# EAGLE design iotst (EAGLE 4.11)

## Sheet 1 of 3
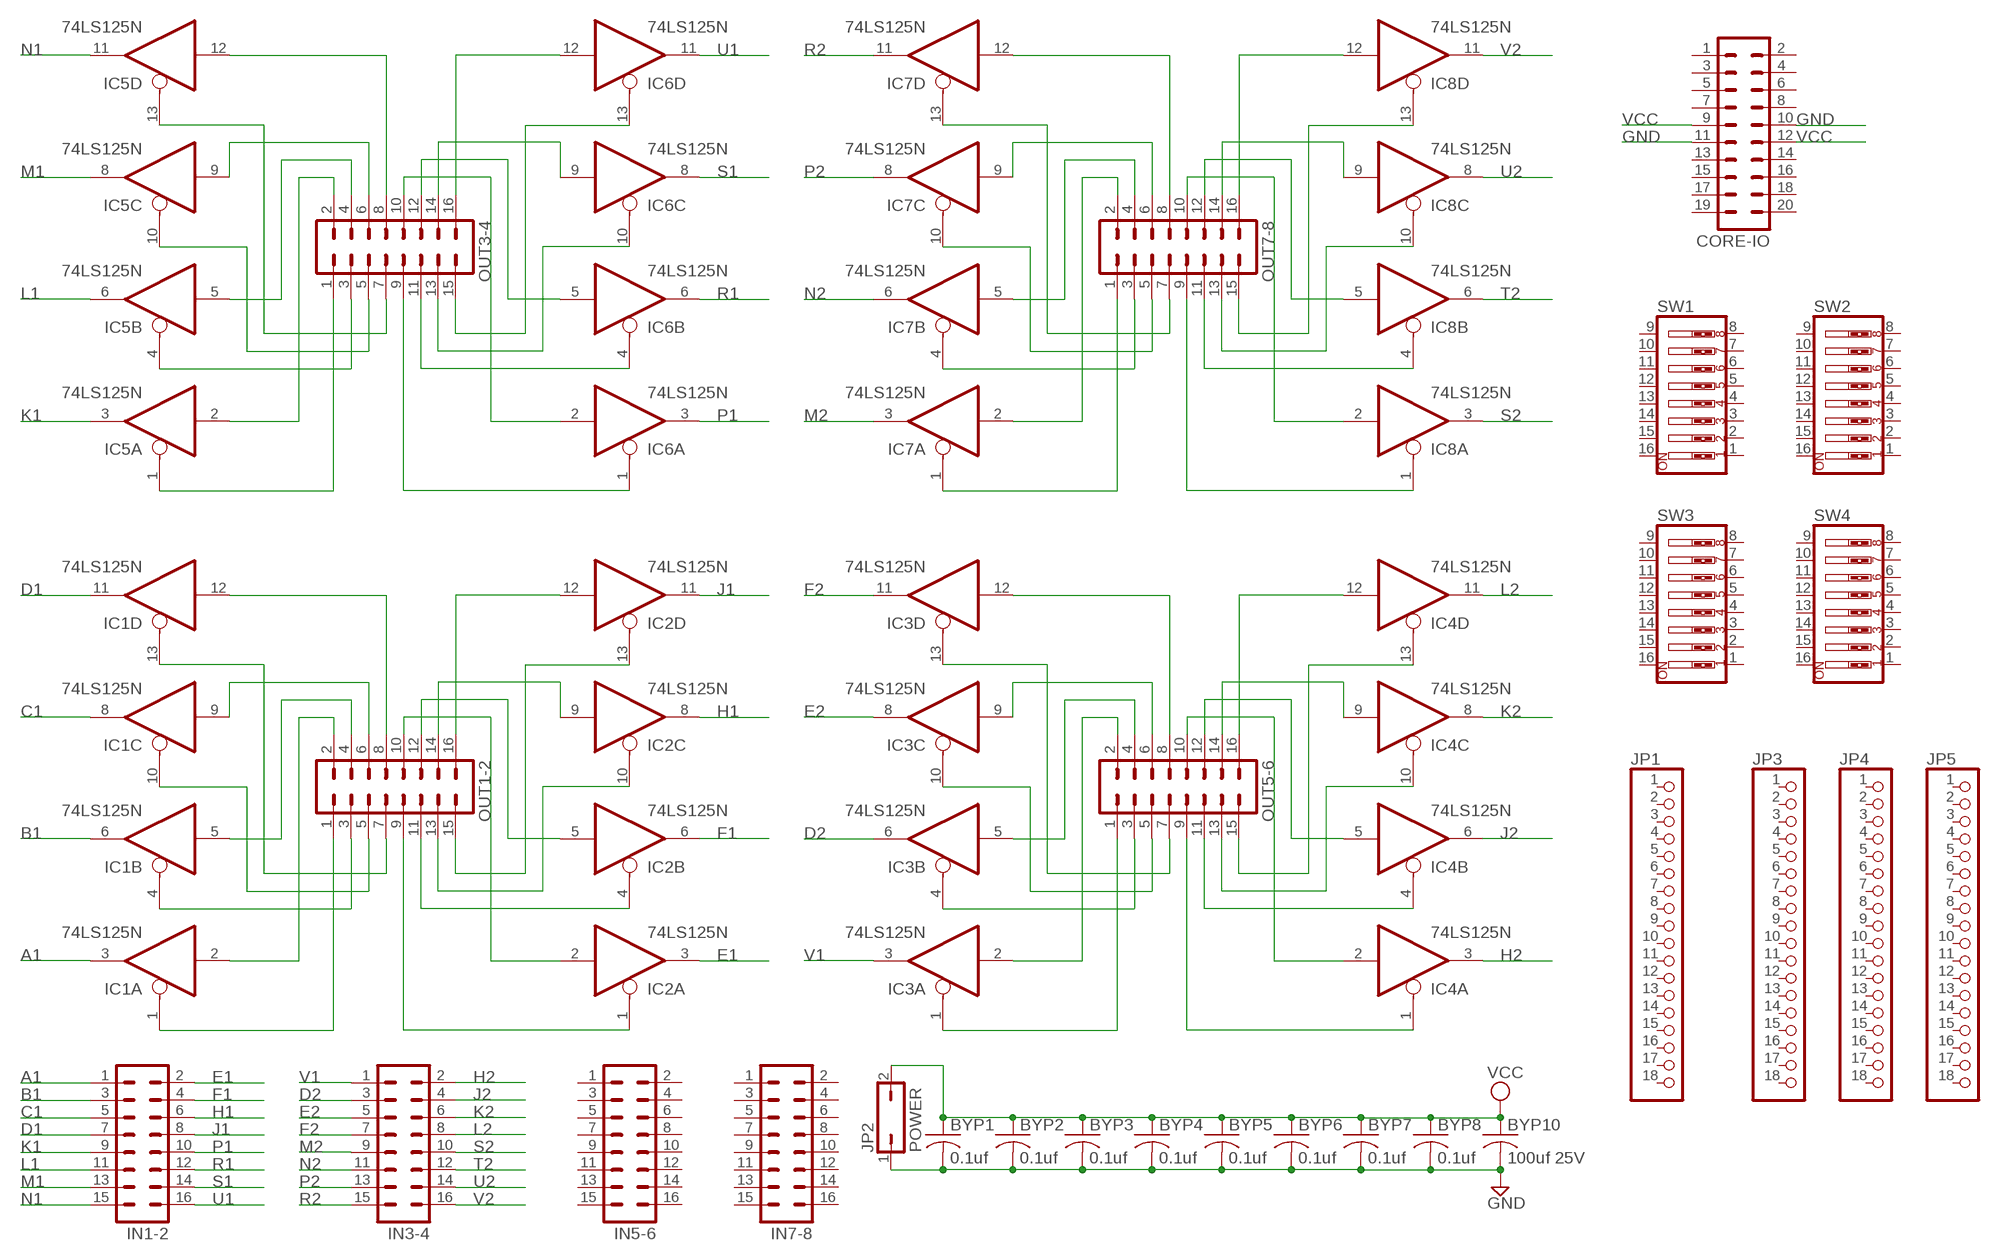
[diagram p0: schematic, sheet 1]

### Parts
BYP1  0.1uf  C-US050-025X075  [C050-025X075]
BYP2  0.1uf  C-US050-025X075  [C050-025X075]
BYP3  0.1uf  C-US050-025X075  [C050-025X075]
BYP4  0.1uf  C-US050-025X075  [C050-025X075]
BYP5  0.1uf  C-US050-025X075  [C050-025X075]
BYP6  0.1uf  C-US050-025X075  [C050-025X075]
BYP7  0.1uf  C-US050-025X075  [C050-025X075]
BYP8  0.1uf  C-US050-025X075  [C050-025X075]
BYP10  100uf 25V  C-US150-064X183  [C150-064X183]
CORE-IO  MA10-2  [MA10-2]
IC1  74LS125N  [DIL14]
IC2  74LS125N  [DIL14]
IC3  74LS125N  [DIL14]
IC4  74LS125N  [DIL14]
IC5  74LS125N  [DIL14]
IC6  74LS125N  [DIL14]
IC7  74LS125N  [DIL14]
IC8  74LS125N  [DIL14]
IN1-2  MA08-2  [MA08-2]
IN3-4  MA08-2  [MA08-2]
IN5-6  MA08-2  [MA08-2]
IN7-8  MA08-2  [MA08-2]
JP1  PINHD-1X18  [1X18]
JP2  POWER  JP1Q  [JP1]
JP3  PINHD-1X18  [1X18]
JP4  PINHD-1X18  [1X18]
JP5  PINHD-1X18  [1X18]
OUT1-2  MA08-2  [MA08-2]
OUT3-4  MA08-2  [MA08-2]
OUT5-6  MA08-2  [MA08-2]
OUT7-8  MA08-2  [MA08-2]
SW1  SW_DIP-8  [EDG-08]
SW2  SW_DIP-8  [EDG-08]
SW3  SW_DIP-8  [EDG-08]
SW4  SW_DIP-8  [EDG-08]

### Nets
A1: IC1.3(A:O) IN1-2.1 ; also sheet 3
B1: IC1.6(B:O) IN1-2.3 ; also sheet 3
C1: IC1.8(C:O) IN1-2.5 ; also sheet 3
D1: IC1.11(D:O) IN1-2.7 ; also sheet 3
D2: IC3.6(B:O) IN3-4.3 ; also sheet 3
E1: IC2.3(A:O) IN1-2.2 ; also sheet 3
E2: IC3.8(C:O) IN3-4.5 ; also sheet 3
F1: IC2.6(B:O) IN1-2.4 ; also sheet 3
F2: IC3.11(D:O) IN3-4.7 ; also sheet 3
GND [Power]: BYP1.2 BYP2.2 BYP3.2 BYP4.2 BYP5.2 BYP6.2 BYP7.2 BYP8.2 BYP10.2 CORE-IO.10 CORE-IO.11 JP2.1 ; also sheet 3
H1: IC2.8(C:O) IN1-2.6 ; also sheet 3
H2: IC4.3(A:O) IN3-4.2 ; also sheet 3
J1: IC2.11(D:O) IN1-2.8 ; also sheet 3
J2: IC4.6(B:O) IN3-4.4 ; also sheet 3
K1: IC5.3(A:O) IN1-2.9 ; also sheet 3
K2: IC4.8(C:O) IN3-4.6 ; also sheet 3
L1: IC5.6(B:O) IN1-2.11 ; also sheet 3
L2: IC4.11(D:O) IN3-4.8 ; also sheet 3
M1: IC5.8(C:O) IN1-2.13 ; also sheet 3
M2: IC7.3(A:O) IN3-4.9 ; also sheet 3
N1: IC5.11(D:O) IN1-2.15 ; also sheet 3
N2: IC7.6(B:O) IN3-4.11 ; also sheet 3
N$53: IC1.1(A:OE) OUT1-2.1
N$54: IC1.4(B:OE) OUT1-2.3
N$55: IC1.10(C:OE) OUT1-2.5
N$56: IC1.13(D:OE) OUT1-2.7
N$57: IC1.2(A:I) OUT1-2.2
N$58: IC1.5(B:I) OUT1-2.4
N$59: IC1.9(C:I) OUT1-2.6
N$60: IC1.12(D:I) OUT1-2.8
N$61: IC3.4(B:OE) OUT5-6.3
N$62: IC2.10(C:OE) OUT1-2.13
N$63: IC2.4(B:OE) OUT1-2.11
N$64: IC2.1(A:OE) OUT1-2.9
N$65: IC2.2(A:I) OUT1-2.10
N$66: IC2.5(B:I) OUT1-2.12
N$67: IC2.9(C:I) OUT1-2.14
N$68: IC2.12(D:I) OUT1-2.16
N$138: IC3.13(D:OE) OUT5-6.7
N$139: IC2.13(D:OE) OUT1-2.15
N$140: IC3.2(A:I) OUT5-6.2
N$141: IC3.5(B:I) OUT5-6.4
N$142: IC3.9(C:I) OUT5-6.6
N$143: IC3.12(D:I) OUT5-6.8
N$144: IC4.10(C:OE) OUT5-6.13
N$145: IC4.4(B:OE) OUT5-6.11
N$146: IC4.1(A:OE) OUT5-6.9
N$147: IC4.2(A:I) OUT5-6.10
N$148: IC4.9(C:I) OUT5-6.14
N$149: IC4.12(D:I) OUT5-6.16
N$150: IC3.1(A:OE) OUT5-6.1
N$151: IC3.10(C:OE) OUT5-6.5
N$152: IC4.5(B:I) OUT5-6.12
N$153: IC4.13(D:OE) OUT5-6.15
N$154: IC5.4(B:OE) OUT3-4.3
N$155: IC5.13(D:OE) OUT3-4.7
N$156: IC5.2(A:I) OUT3-4.2
N$157: IC5.5(B:I) OUT3-4.4
N$158: IC5.9(C:I) OUT3-4.6
N$159: IC5.12(D:I) OUT3-4.8
N$160: IC6.10(C:OE) OUT3-4.13
N$161: IC6.4(B:OE) OUT3-4.11
N$162: IC6.1(A:OE) OUT3-4.9
N$163: IC6.2(A:I) OUT3-4.10
N$164: IC6.9(C:I) OUT3-4.14
N$165: IC6.12(D:I) OUT3-4.16
N$166: IC5.1(A:OE) OUT3-4.1
N$167: IC5.10(C:OE) OUT3-4.5
N$168: IC6.5(B:I) OUT3-4.12
N$169: IC6.13(D:OE) OUT3-4.15
N$170: IC7.4(B:OE) OUT7-8.3
N$171: IC7.13(D:OE) OUT7-8.7
N$172: IC7.2(A:I) OUT7-8.2
N$173: IC7.5(B:I) OUT7-8.4
N$174: IC7.9(C:I) OUT7-8.6
N$175: IC7.12(D:I) OUT7-8.8
N$176: IC8.10(C:OE) OUT7-8.13
N$177: IC8.4(B:OE) OUT7-8.11
N$178: IC8.1(A:OE) OUT7-8.9
N$179: IC8.2(A:I) OUT7-8.10
N$180: IC8.9(C:I) OUT7-8.14
N$181: IC8.12(D:I) OUT7-8.16
N$182: IC7.1(A:OE) OUT7-8.1
N$183: IC7.10(C:OE) OUT7-8.5
N$184: IC8.5(B:I) OUT7-8.12
N$185: IC8.13(D:OE) OUT7-8.15
P1: IC6.3(A:O) IN1-2.10 ; also sheet 3
P2: IC7.8(C:O) IN3-4.13 ; also sheet 3
R1: IC6.6(B:O) IN1-2.12 ; also sheet 3
R2: IC7.11(D:O) IN3-4.15 ; also sheet 3
S1: IC6.8(C:O) IN1-2.14 ; also sheet 3
S2: IC8.3(A:O) IN3-4.10 ; also sheet 3
T2: IC8.6(B:O) IN3-4.12 ; also sheet 3
U1: IC6.11(D:O) IN1-2.16 ; also sheet 3
U2: IC8.8(C:O) IN3-4.14 ; also sheet 3
V1: IC3.3(A:O) IN3-4.1 ; also sheet 3
V2: IC8.11(D:O) IN3-4.16 ; also sheet 3
VCC [Power]: BYP1.1 BYP2.1 BYP3.1 BYP4.1 BYP5.1 BYP6.1 BYP7.1 BYP8.1 BYP10.1 CORE-IO.9 CORE-IO.12 JP2.2 ; also sheet 3
Unconnected: CORE-IO.1 CORE-IO.2 CORE-IO.3 CORE-IO.4 CORE-IO.5 CORE-IO.6 CORE-IO.7 CORE-IO.8 CORE-IO.13 CORE-IO.14 CORE-IO.15 CORE-IO.16 CORE-IO.17 CORE-IO.18 CORE-IO.19 CORE-IO.20 IN5-6.1 IN5-6.2 IN5-6.3 IN5-6.4 IN5-6.5 IN5-6.6 IN5-6.7 IN5-6.8 IN5-6.9 IN5-6.10 IN5-6.11 IN5-6.12 IN5-6.13 IN5-6.14 IN5-6.15 IN5-6.16 IN7-8.1 IN7-8.2 IN7-8.3 IN7-8.4 IN7-8.5 IN7-8.6 IN7-8.7 IN7-8.8 IN7-8.9 IN7-8.10 IN7-8.11 IN7-8.12 IN7-8.13 IN7-8.14 IN7-8.15 IN7-8.16 JP1.1 JP1.2 JP1.3 JP1.4 JP1.5 JP1.6 JP1.7 JP1.8 JP1.9 JP1.10 JP1.11 JP1.12 JP1.13 JP1.14 JP1.15 JP1.16 JP1.17 JP1.18 JP3.1 JP3.2 JP3.3 JP3.4 JP3.5 JP3.6 JP3.7 JP3.8 JP3.9 JP3.10 JP3.11 JP3.12 JP3.13 JP3.14 JP3.15 JP3.16 JP3.17 JP3.18 JP4.1 JP4.2 JP4.3 JP4.4 JP4.5 JP4.6 JP4.7 JP4.8 JP4.9 JP4.10 JP4.11 JP4.12 JP4.13 JP4.14 JP4.15 JP4.16 JP4.17 JP4.18 JP5.1 JP5.2 JP5.3 JP5.4 JP5.5 JP5.6 JP5.7 JP5.8 JP5.9 JP5.10 JP5.11 JP5.12 JP5.13 JP5.14 JP5.15 JP5.16 JP5.17 JP5.18 SW1.1 SW1.2 SW1.3 SW1.4 SW1.5 SW1.6 SW1.7 SW1.8 SW1.9 SW1.10 SW1.11 SW1.12 SW1.13 SW1.14 SW1.15 SW1.16 SW2.1 SW2.2 SW2.3 SW2.4 SW2.5 SW2.6 SW2.7 SW2.8 SW2.9 SW2.10 SW2.11 SW2.12 SW2.13 SW2.14 SW2.15 SW2.16 SW3.1 SW3.2 SW3.3 SW3.4 SW3.5 SW3.6 SW3.7 SW3.8 SW3.9 SW3.10 SW3.11 SW3.12 SW3.13 SW3.14 SW3.15 SW3.16 SW4.1 SW4.2 SW4.3 SW4.4 SW4.5 SW4.6 SW4.7 SW4.8 SW4.9 SW4.10 SW4.11 SW4.12 SW4.13 SW4.14 SW4.15 SW4.16

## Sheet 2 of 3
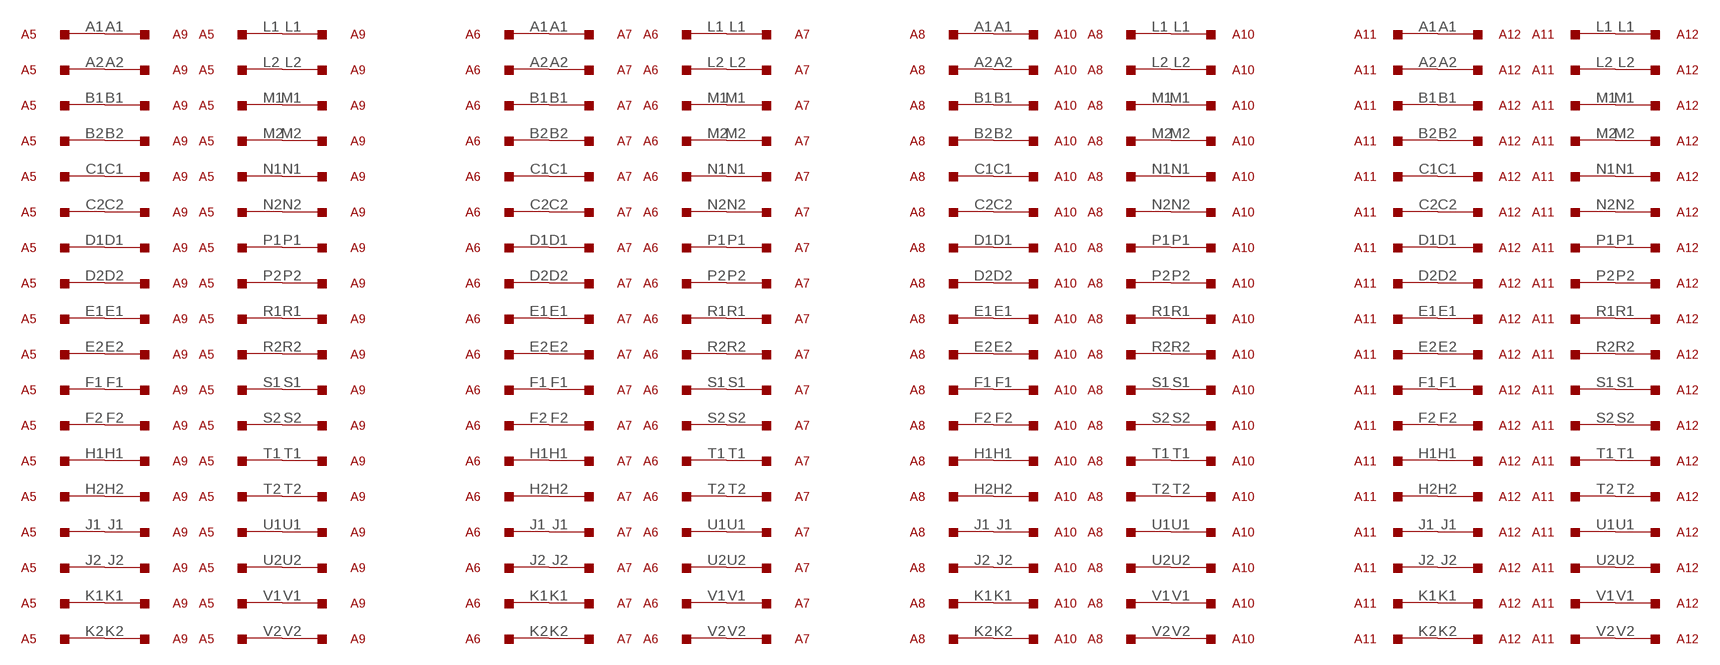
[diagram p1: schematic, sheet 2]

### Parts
A5  M916  [H807]
A6  M916  [H807]
A7  M916  [H807]
A8  M916  [H807]
A9  M916  [H807]
A10  M916  [H807]
A11  M916  [H807]
A12  M916  [H807]

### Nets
N$26: A5.L1 A9.L1
N$33: A5.L2 A9.L2
N$34: A5.M1 A9.M1
N$35: A5.M2 A9.M2
N$36: A5.N1 A9.N1
N$49: A5.N2 A9.N2
N$50: A5.P1 A9.P1
N$51: A5.P2 A9.P2
N$52: A5.R1 A9.R1
N$69: A5.R2 A9.R2
N$70: A5.S1 A9.S1
N$71: A5.S2 A9.S2
N$72: A5.T1 A9.T1
N$73: A5.T2 A9.T2
N$74: A5.U1 A9.U1
N$75: A5.U2 A9.U2
N$76: A5.V1 A9.V1
N$81: A5.V2 A9.V2
N$82: A5.A1 A9.A1
N$83: A5.A2 A9.A2
N$84: A5.B1 A9.B1
N$85: A5.B2 A9.B2
N$86: A5.C1 A9.C1
N$87: A5.C2 A9.C2
N$88: A5.D1 A9.D1
N$89: A5.D2 A9.D2
N$90: A5.E1 A9.E1
N$91: A5.E2 A9.E2
N$92: A5.F1 A9.F1
N$93: A5.F2 A9.F2
N$95: A5.H1 A9.H1
N$96: A5.H2 A9.H2
N$97: A5.J1 A9.J1
N$98: A5.J2 A9.J2
N$99: A5.K1 A9.K1
N$100: A5.K2 A9.K2
N$113: A6.L1 A7.L1
N$114: A6.L2 A7.L2
N$115: A6.M1 A7.M1
N$116: A6.M2 A7.M2
N$117: A6.N1 A7.N1
N$118: A6.N2 A7.N2
N$119: A6.P1 A7.P1
N$120: A6.P2 A7.P2
N$121: A6.R1 A7.R1
N$122: A6.R2 A7.R2
N$123: A6.S1 A7.S1
N$137: A6.S2 A7.S2
N$186: A6.T1 A7.T1
N$187: A6.T2 A7.T2
N$188: A6.U1 A7.U1
N$189: A6.U2 A7.U2
N$190: A6.V1 A7.V1
N$191: A6.V2 A7.V2
N$192: A6.A1 A7.A1
N$193: A6.A2 A7.A2
N$194: A6.B1 A7.B1
N$195: A6.B2 A7.B2
N$196: A6.C1 A7.C1
N$197: A6.C2 A7.C2
N$198: A6.D1 A7.D1
N$199: A6.D2 A7.D2
N$200: A6.E1 A7.E1
N$201: A6.E2 A7.E2
N$202: A6.F1 A7.F1
N$203: A6.F2 A7.F2
N$204: A6.H1 A7.H1
N$205: A6.H2 A7.H2
N$206: A6.J1 A7.J1
N$207: A6.J2 A7.J2
N$208: A6.K1 A7.K1
N$209: A6.K2 A7.K2
N$210: A8.L1 A10.L1
N$211: A8.L2 A10.L2
N$212: A8.M1 A10.M1
N$213: A8.M2 A10.M2
N$214: A8.N1 A10.N1
N$215: A8.N2 A10.N2
N$216: A8.P1 A10.P1
N$217: A8.P2 A10.P2
N$218: A8.R1 A10.R1
N$219: A8.R2 A10.R2
N$220: A8.S1 A10.S1
N$221: A8.S2 A10.S2
N$222: A8.T1 A10.T1
N$223: A8.T2 A10.T2
N$224: A8.U1 A10.U1
N$225: A8.U2 A10.U2
N$226: A8.V1 A10.V1
N$227: A8.V2 A10.V2
N$228: A8.A1 A10.A1
N$229: A8.A2 A10.A2
N$230: A8.B1 A10.B1
N$231: A8.B2 A10.B2
N$232: A8.C1 A10.C1
N$233: A8.C2 A10.C2
N$234: A8.D1 A10.D1
N$235: A8.D2 A10.D2
N$236: A8.E1 A10.E1
N$237: A8.E2 A10.E2
N$238: A8.F1 A10.F1
N$239: A8.F2 A10.F2
N$240: A8.H1 A10.H1
N$241: A8.H2 A10.H2
N$242: A8.J1 A10.J1
N$243: A8.J2 A10.J2
N$244: A8.K1 A10.K1
N$245: A8.K2 A10.K2
N$246: A11.L1 A12.L1
N$247: A11.L2 A12.L2
N$248: A11.M1 A12.M1
N$249: A11.M2 A12.M2
N$250: A11.N1 A12.N1
N$251: A11.N2 A12.N2
N$252: A11.P1 A12.P1
N$253: A11.P2 A12.P2
N$254: A11.R1 A12.R1
N$255: A11.R2 A12.R2
N$256: A11.S1 A12.S1
N$257: A11.S2 A12.S2
N$258: A11.T1 A12.T1
N$259: A11.T2 A12.T2
N$260: A11.U1 A12.U1
N$261: A11.U2 A12.U2
N$262: A11.V1 A12.V1
N$263: A11.V2 A12.V2
N$264: A11.A1 A12.A1
N$265: A11.A2 A12.A2
N$266: A11.B1 A12.B1
N$267: A11.B2 A12.B2
N$268: A11.C1 A12.C1
N$269: A11.C2 A12.C2
N$270: A11.D1 A12.D1
N$271: A11.D2 A12.D2
N$272: A11.E1 A12.E1
N$273: A11.E2 A12.E2
N$274: A11.F1 A12.F1
N$275: A11.F2 A12.F2
N$276: A11.H1 A12.H1
N$277: A11.H2 A12.H2
N$278: A11.J1 A12.J1
N$279: A11.J2 A12.J2
N$280: A11.K1 A12.K1
N$281: A11.K2 A12.K2

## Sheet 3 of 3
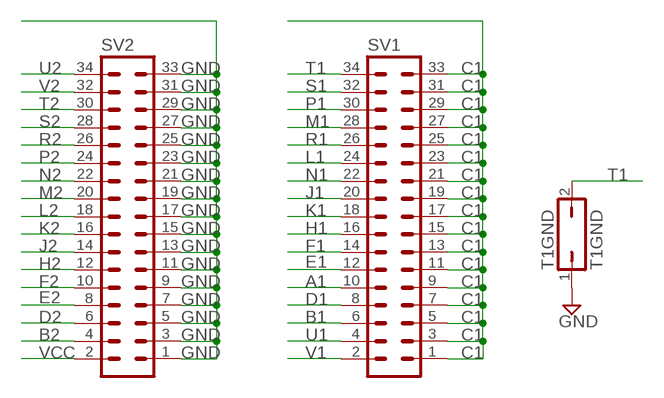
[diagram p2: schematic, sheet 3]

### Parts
SV1  MA17-2  [MA17-2]
SV2  MA17-2  [MA17-2]
T1GND  T1GND  JP1Q  [JP1]

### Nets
A1: SV1.10 ; also sheet 1
B1: SV1.6 ; also sheet 1
B2: SV2.4
C1: SV1.1 SV1.3 SV1.5 SV1.7 SV1.9 SV1.11 SV1.13 SV1.15 SV1.17 SV1.19 SV1.21 SV1.23 SV1.25 SV1.27 SV1.29 SV1.31 SV1.33 ; also sheet 1
D1: SV1.8 ; also sheet 1
D2: SV2.6 ; also sheet 1
E1: SV1.12 ; also sheet 1
E2: SV2.8 ; also sheet 1
F1: SV1.14 ; also sheet 1
F2: SV2.10 ; also sheet 1
GND [Power]: SV2.1 SV2.3 SV2.5 SV2.7 SV2.9 SV2.11 SV2.13 SV2.15 SV2.17 SV2.19 SV2.21 SV2.23 SV2.25 SV2.27 SV2.29 SV2.31 SV2.33 T1GND.1 ; also sheet 1
H1: SV1.16 ; also sheet 1
H2: SV2.12 ; also sheet 1
J1: SV1.20 ; also sheet 1
J2: SV2.14 ; also sheet 1
K1: SV1.18 ; also sheet 1
K2: SV2.16 ; also sheet 1
L1: SV1.24 ; also sheet 1
L2: SV2.18 ; also sheet 1
M1: SV1.28 ; also sheet 1
M2: SV2.20 ; also sheet 1
N1: SV1.22 ; also sheet 1
N2: SV2.22 ; also sheet 1
P1: SV1.30 ; also sheet 1
P2: SV2.24 ; also sheet 1
R1: SV1.26 ; also sheet 1
R2: SV2.26 ; also sheet 1
S1: SV1.32 ; also sheet 1
S2: SV2.28 ; also sheet 1
T1: SV1.34 T1GND.2
T2: SV2.30 ; also sheet 1
U1: SV1.4 ; also sheet 1
U2: SV2.34 ; also sheet 1
V1: SV1.2 ; also sheet 1
V2: SV2.32 ; also sheet 1
VCC [Power]: SV2.2 ; also sheet 1

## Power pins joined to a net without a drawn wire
GND: IC1.7(P:GND) IC2.7(P:GND) IC3.7(P:GND) IC4.7(P:GND) IC5.7(P:GND) IC6.7(P:GND) IC7.7(P:GND) IC8.7(P:GND)
VCC: IC1.14(P:VCC) IC2.14(P:VCC) IC3.14(P:VCC) IC4.14(P:VCC) IC5.14(P:VCC) IC6.14(P:VCC) IC7.14(P:VCC) IC8.14(P:VCC)

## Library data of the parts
A5-A12 = dec-m:M916: Simple 36 pin connector/wire cable
BYP1-BYP8 BYP10 = rcl:C-US: CAPACITOR, American symbol
CORE-IO = con-lstb:MA10-2: PIN HEADER
IC1-IC8 = 74xx-jameco:74*125: Quad bus BUFFER, 3-state
IN1-2 IN3-4 IN5-6 IN7-8 OUT1-2 OUT3-4 OUT5-6 OUT7-8 = con-lstb:MA08-2: PIN HEADER
JP1 JP3-JP5 = pinhead:PINHD-1X18: PIN HEADER
JP2 T1GND = jumper:JP1Q: JUMPER
SV1 SV2 = con-lstb:MA17-2: PIN HEADER
SW1-SW4 = special:SW_DIP-8: DIP SWITCH

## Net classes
1 Power: width 0.508 mm, drill 0.254 mm, clearance 0.254 mm

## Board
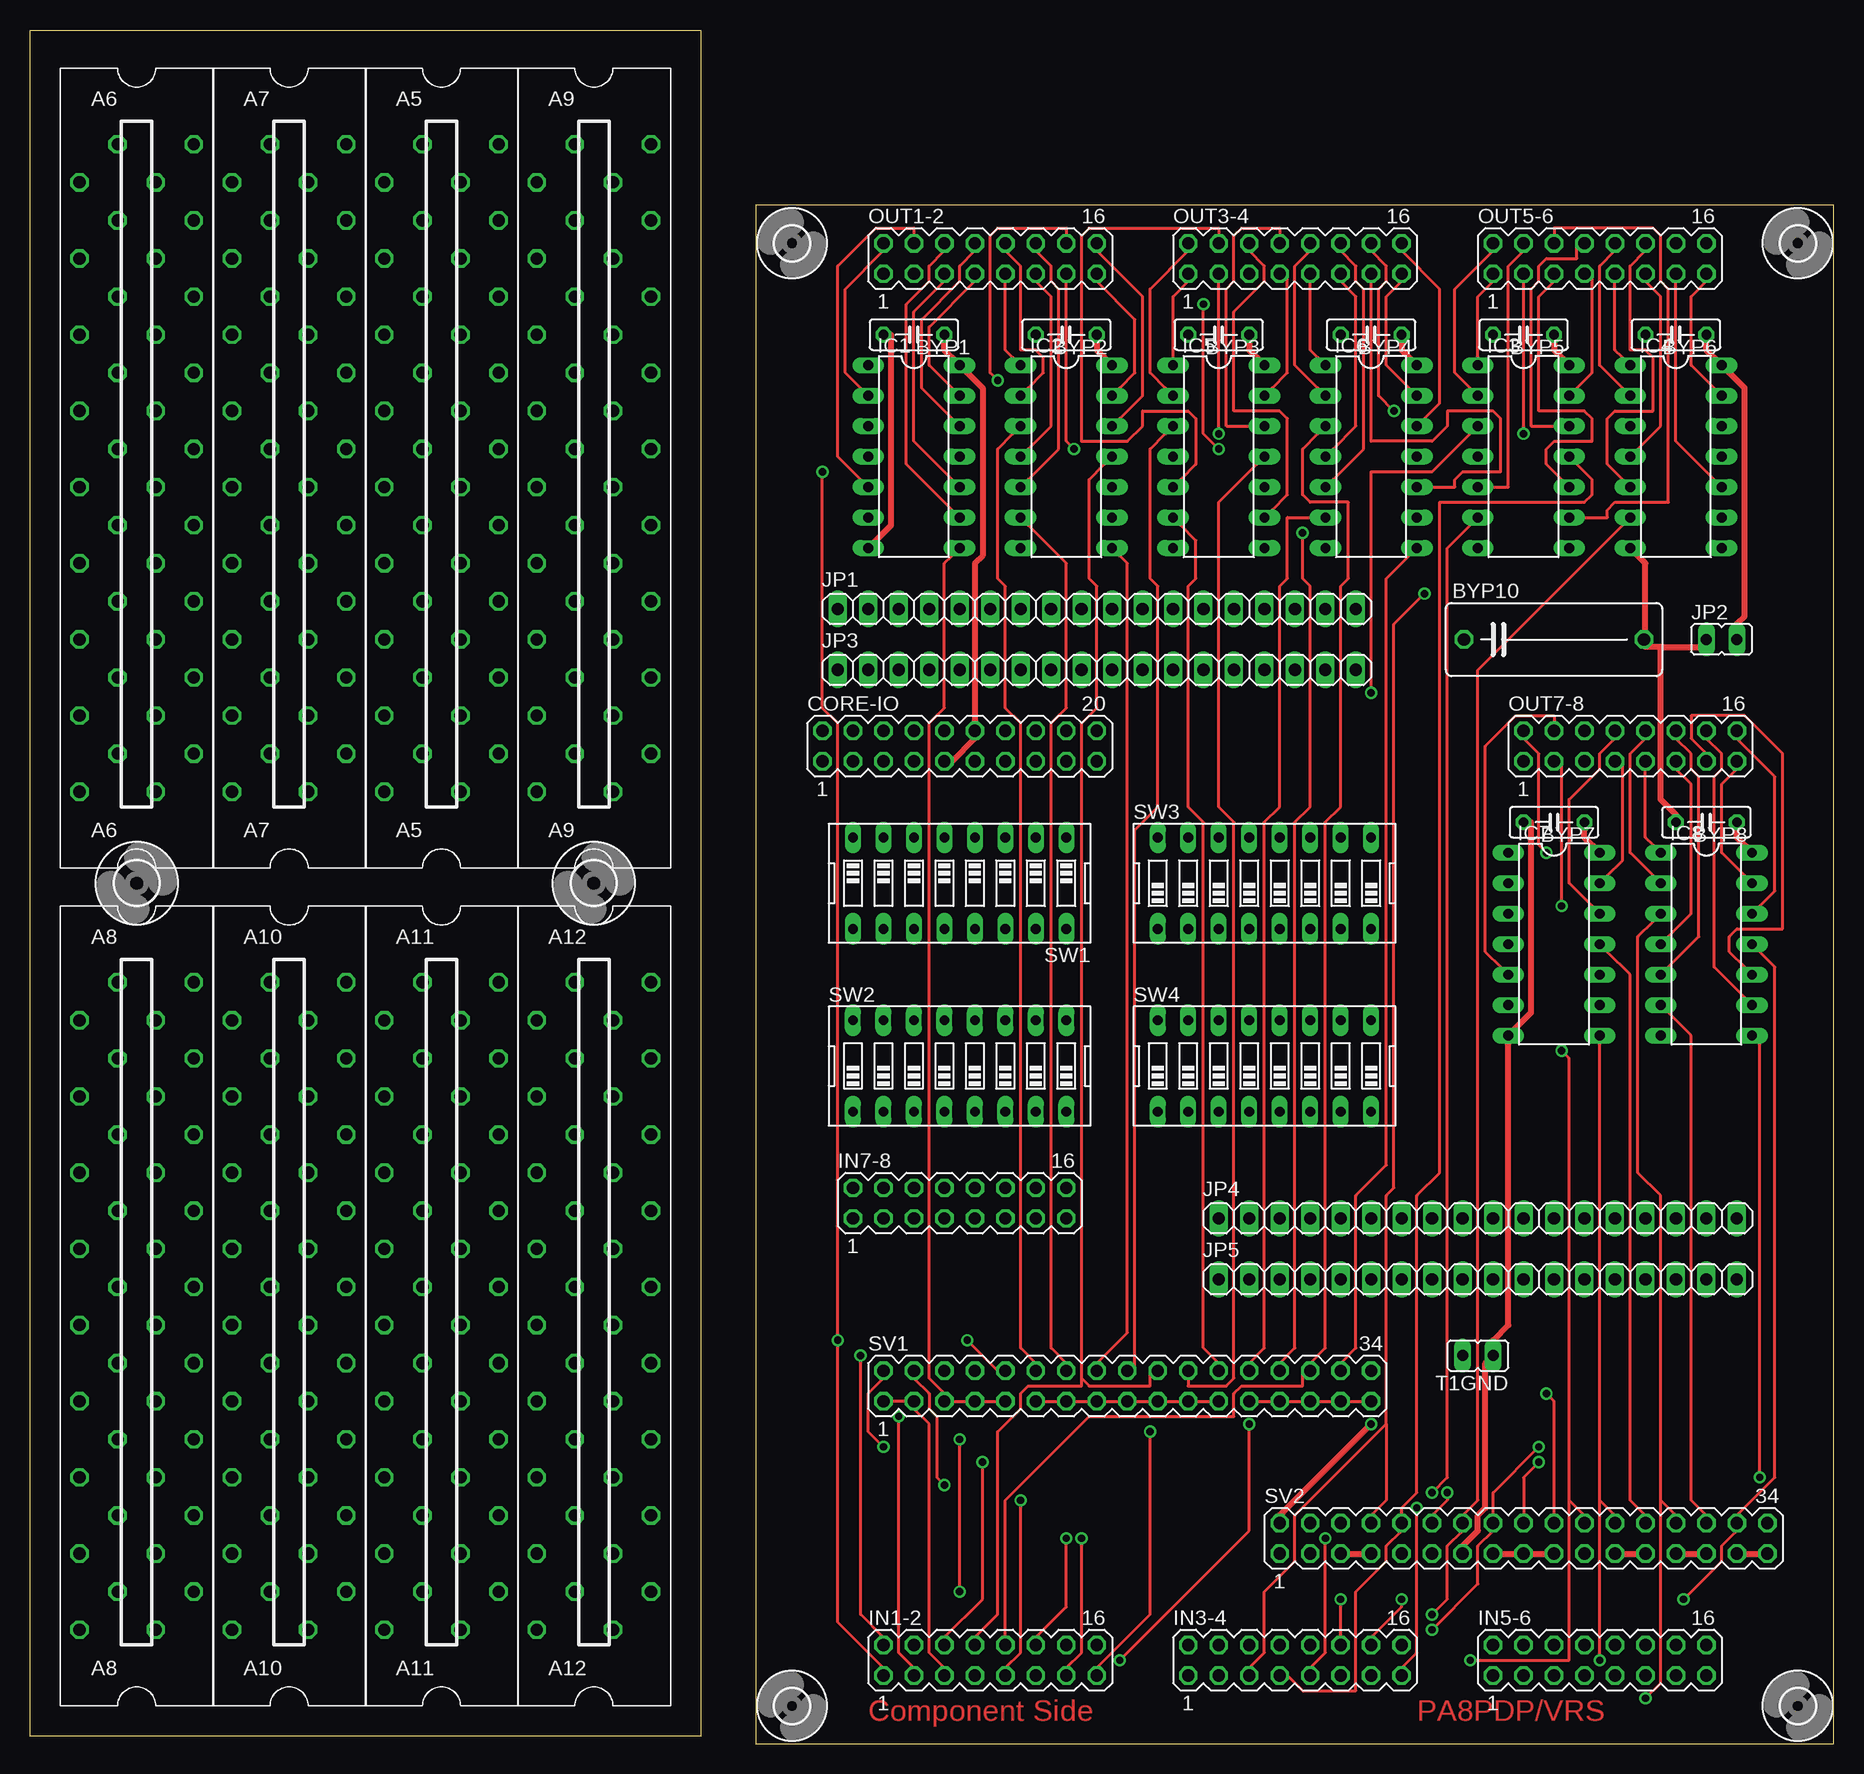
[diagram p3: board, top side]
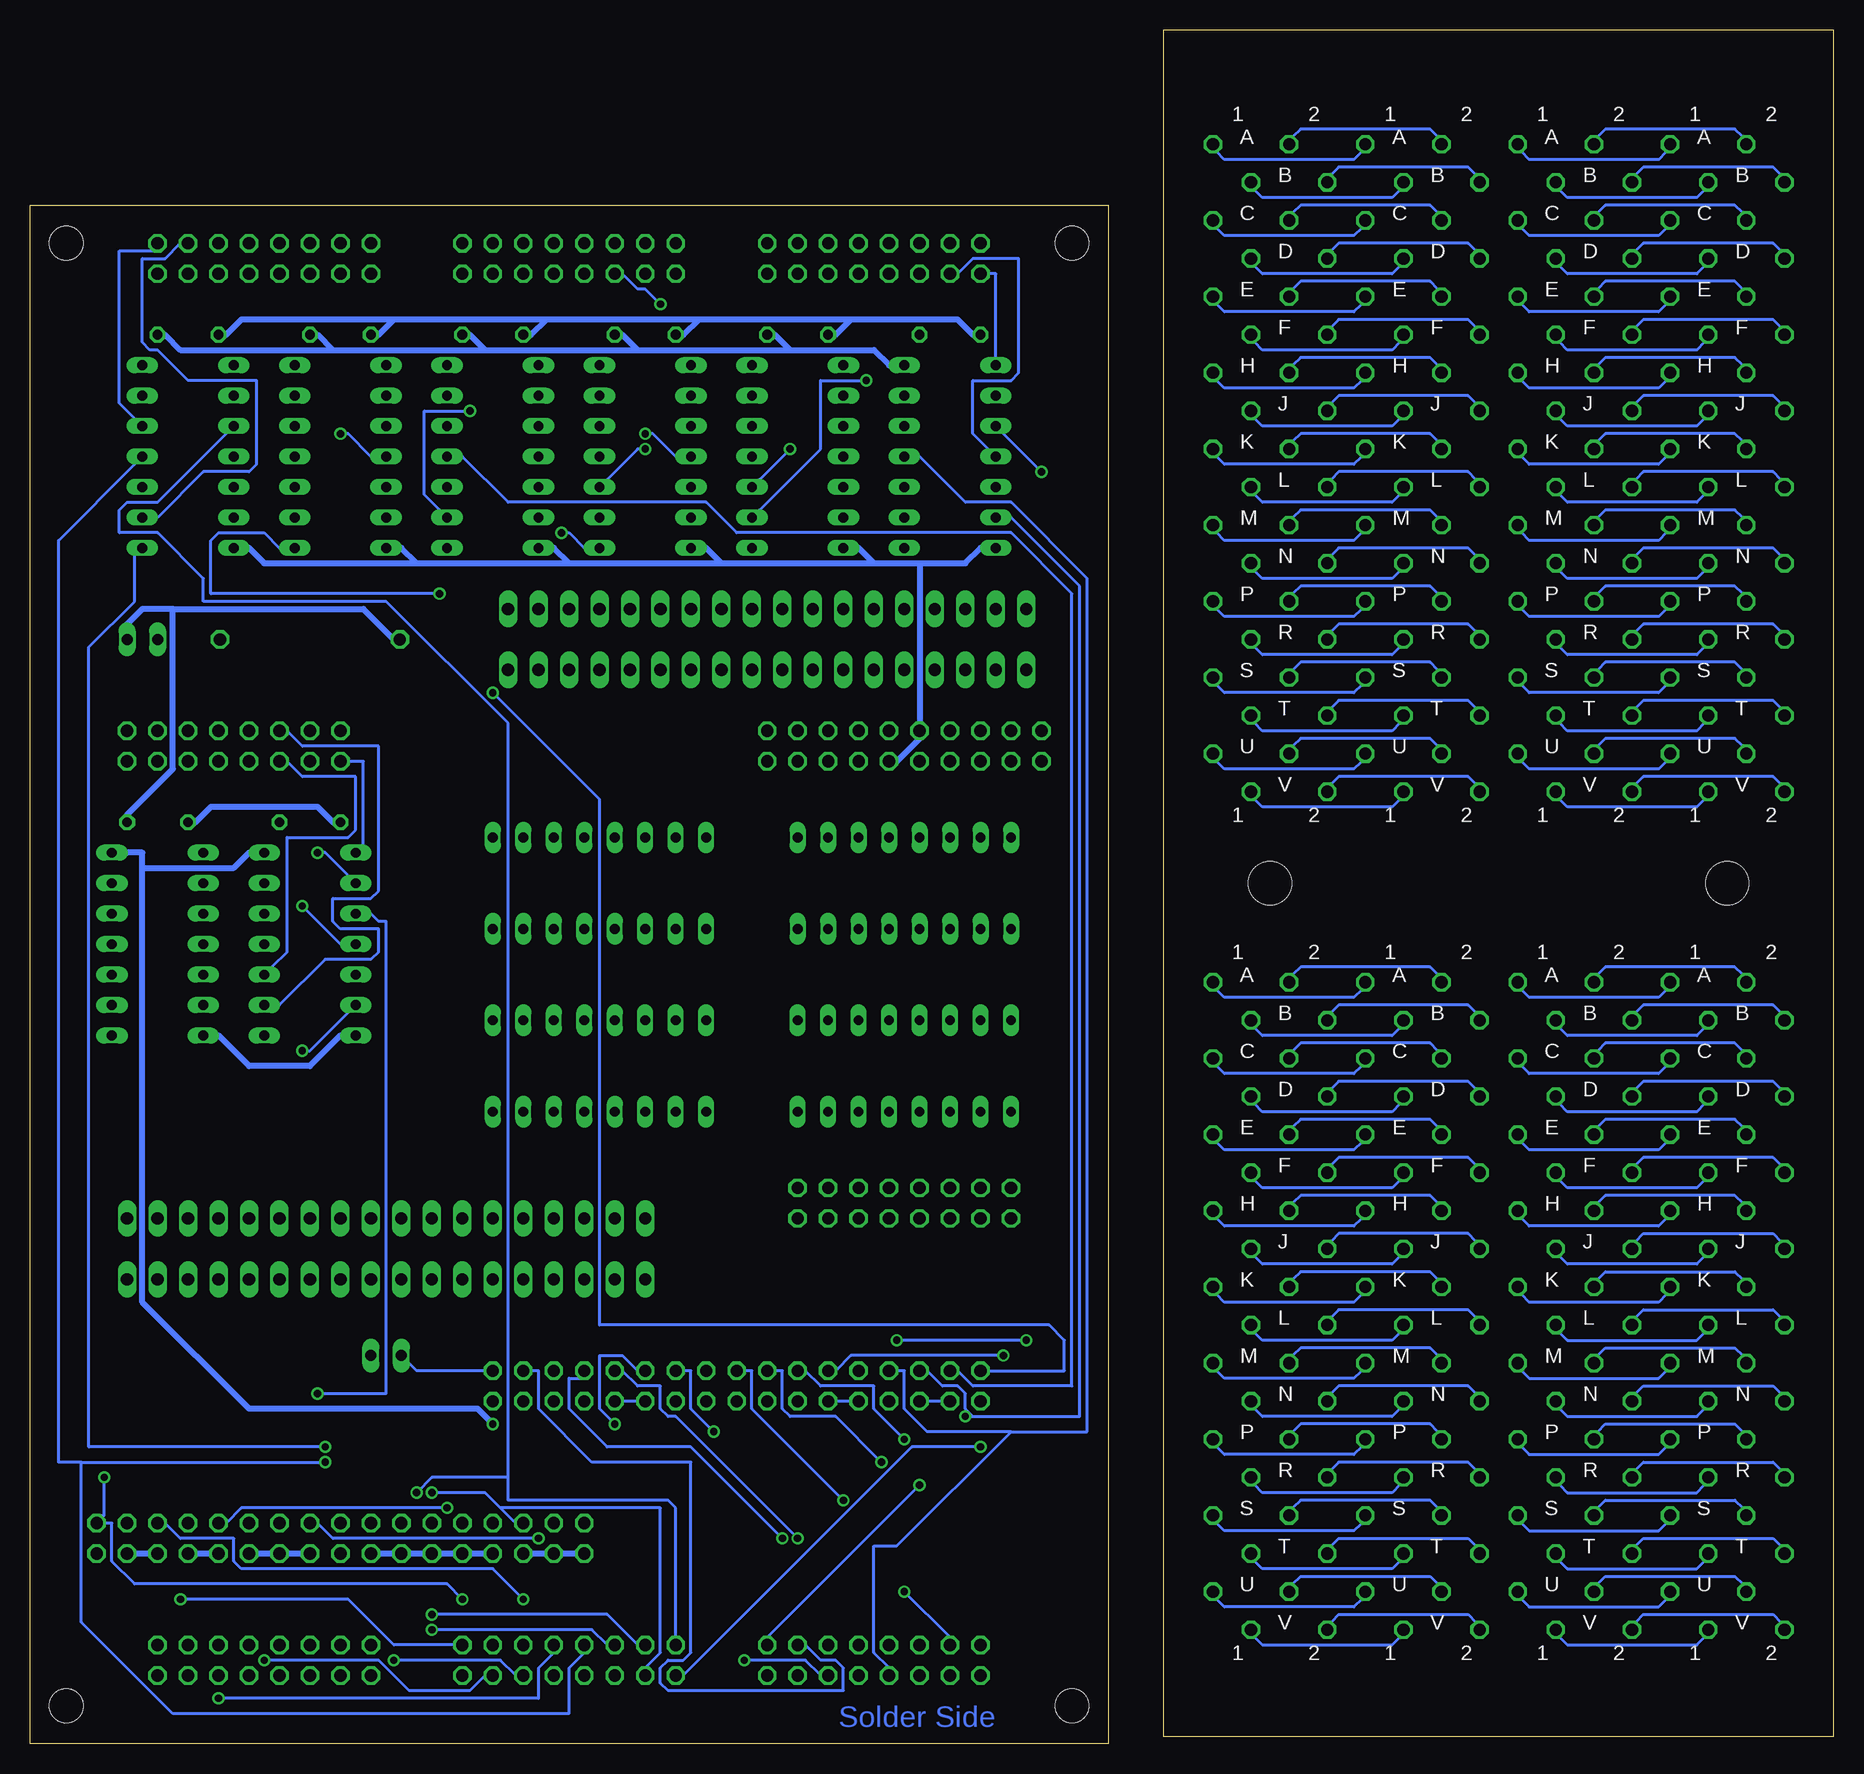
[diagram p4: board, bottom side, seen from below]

Size 150.33 x 142.86 mm. Coordinates in mm from the lower left corner, seen from the top.
Outline: 60.49,128.25 60.49,0 150.33,0 150.33,128.25 60.49,128.25
Outline: 55.88,0.62 0,0.62 0,142.86 55.88,142.86 55.88,0.62
Copper layers (1*16): Top 0.035mm / dielectric 1.5mm / Bottom 0.035mm
Design rules "olimex10mil": minimum track width 10mil, minimum drill 24mil, track to track 10mil, track to pad 10mil, pad to pad 10mil, via to via 10mil, smd to smd 10mil, copper to edge 40mil, drill to drill 10mil, minimum pad ring 10mil, minimum via ring 8mil, stop-mask expansion 0mil, vias tented up to drill 0mil, thermal gap 10mil

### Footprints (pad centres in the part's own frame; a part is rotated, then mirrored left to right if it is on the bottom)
H807 = drill 1.016 octagon: A1 4.763,28.575; A2 -1.587,28.575; B1 1.587,25.4; B2 -4.763,25.4; C1 4.763,22.225; C2 -1.587,22.225; D1 1.587,19.05; D2 -4.763,19.05; E1 4.763,15.875; E2 -1.587,15.875; F1 1.587,12.7; F2 -4.763,12.7; H1 4.763,9.525; H2 -1.587,9.525; J1 1.587,6.35; J2 -4.763,6.35; K1 4.763,3.175; K2 -1.587,3.175; L1 1.587,0; L2 -4.763,0; M1 4.763,-3.175; M2 -1.587,-3.175; N1 1.587,-6.35; N2 -4.763,-6.35; P1 4.763,-9.525; P2 -1.587,-9.525; R1 1.587,-12.7; R2 -4.763,-12.7; S1 4.763,-15.875; S2 -1.587,-15.875; T1 1.587,-19.05; T2 -4.763,-19.05; U1 4.763,-22.225; U2 -1.587,-22.225; V1 1.587,-25.4; V2 -4.763,-25.4
C050-025X075 = drill 0.813 octagon: 1 -2.54,0; 2 2.54,0
C150-064X183 = drill 1.016 octagon: 1 -7.493,0; 2 7.493,0
MA10-2 = drill 1.016 octagon: 1 -11.43,-1.27; 2 -11.43,1.27; 3 -8.89,-1.27; 4 -8.89,1.27; 5 -6.35,-1.27; 6 -6.35,1.27; 7 -3.81,-1.27; 8 -3.81,1.27; 9 -1.27,-1.27; 10 -1.27,1.27; 11 1.27,-1.27; 12 1.27,1.27; 13 3.81,-1.27; 14 3.81,1.27; 15 6.35,-1.27; 16 6.35,1.27; 17 8.89,-1.27; 18 8.89,1.27; 19 11.43,-1.27; 20 11.43,1.27
DIL14 = drill 0.813 long: 1 -7.62,-3.81; 2 -5.08,-3.81; 3 -2.54,-3.81; 4 0,-3.81; 5 2.54,-3.81; 6 5.08,-3.81; 7 7.62,-3.81; 8 7.62,3.81; 9 5.08,3.81; 10 2.54,3.81; 11 0,3.81; 12 -2.54,3.81; 13 -5.08,3.81; 14 -7.62,3.81
MA08-2 = drill 1.016 octagon: 1 -8.89,-1.27; 2 -8.89,1.27; 3 -6.35,-1.27; 4 -6.35,1.27; 5 -3.81,-1.27; 6 -3.81,1.27; 7 -1.27,-1.27; 8 -1.27,1.27; 9 1.27,-1.27; 10 1.27,1.27; 11 3.81,-1.27; 12 3.81,1.27; 13 6.35,-1.27; 14 6.35,1.27; 15 8.89,-1.27; 16 8.89,1.27
1X18 = drill 1.016 long: 1 -21.59,0; 2 -19.05,0; 3 -16.51,0; 4 -13.97,0; 5 -11.43,0; 6 -8.89,0; 7 -6.35,0; 8 -3.81,0; 9 -1.27,0; 10 1.27,0; 11 3.81,0; 12 6.35,0; 13 8.89,0; 14 11.43,0; 15 13.97,0; 16 16.51,0; 17 19.05,0; 18 21.59,0
JP1 = drill 0.914 long: 1 0,-1.27; 2 0,1.27
MA17-2 = drill 1.016 octagon: 1 -20.32,-1.27; 2 -20.32,1.27; 3 -17.78,-1.27; 4 -17.78,1.27; 5 -15.24,-1.27; 6 -15.24,1.27; 7 -12.7,-1.27; 8 -12.7,1.27; 9 -10.16,-1.27; 10 -10.16,1.27; 11 -7.62,-1.27; 12 -7.62,1.27; 13 -5.08,-1.27; 14 -5.08,1.27; 15 -2.54,-1.27; 16 -2.54,1.27; 17 0,-1.27; 18 0,1.27; 19 2.54,-1.27; 20 2.54,1.27; 21 5.08,-1.27; 22 5.08,1.27; 23 7.62,-1.27; 24 7.62,1.27; 25 10.16,-1.27; 26 10.16,1.27; 27 12.7,-1.27; 28 12.7,1.27; 29 15.24,-1.27; 30 15.24,1.27; 31 17.78,-1.27; 32 17.78,1.27; 33 20.32,-1.27; 34 20.32,1.27
EDG-08 = drill 0.813 long: 1 -8.89,-3.81; 2 -6.35,-3.81; 3 -3.81,-3.81; 4 -1.27,-3.81; 5 1.27,-3.81; 6 3.81,-3.81; 7 6.35,-3.81; 8 8.89,-3.81; 9 8.89,3.81; 10 6.35,3.81; 11 3.81,3.81; 12 1.27,3.81; 13 -1.27,3.81; 14 -3.81,3.81; 15 -6.35,3.81; 16 -8.89,3.81
2,8 = hole 2.8: 0,0
3,6 = hole 3.6: 0,0

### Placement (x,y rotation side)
A5  34.29,104.76 0 top
A6  8.89,104.76 0 top
A7  21.59,104.76 0 top
A8  8.89,34.91 0 top
A9  46.99,104.76 0 top
A10  21.59,34.91 0 top
A11  34.29,34.91 0 top
A12  46.99,34.91 0 top
BYP1  73.66,117.46 180 top
BYP2  86.36,117.46 180 top
BYP3  99.06,117.46 180 top
BYP4  111.76,117.46 180 top
BYP5  124.46,117.46 180 top
BYP6  137.16,117.46 180 top
BYP7  127,76.82 180 top
BYP8  139.7,76.82 180 top
BYP10  127,92.06 0 top
CORE-IO  77.47,83.17 0 top
IC1  73.66,107.3 270 top
IC2  86.36,107.3 270 top
IC3  124.46,107.3 270 top
IC4  137.16,107.3 270 top
IC5  99.06,107.3 270 top
IC6  111.76,107.3 270 top
IC7  127,66.66 270 top
IC8  139.7,66.66 270 top
IN1-2  80.01,6.97 0 top
IN3-4  105.41,6.97 0 top
IN5-6  130.81,6.97 0 top
IN7-8  77.47,45.07 0 top
JP1  88.9,94.6 0 top
JP2  140.97,92.06 270 top
JP3  88.9,89.52 0 top
JP4  120.65,43.8 0 top
JP5  120.65,38.72 0 top
OUT1-2  80.01,123.81 0 top
OUT3-4  105.41,123.81 0 top
OUT5-6  130.81,123.81 0 top
OUT7-8  133.35,83.17 0 top
SV1  91.44,29.83 0 top
SV2  124.46,17.13 0 top
SW1  77.47,71.74 180 top
SW2  77.47,56.5 0 top
SW3  102.87,71.74 0 top
SW4  102.87,56.5 0 top
T1GND  120.65,32.37 90 top
U$1  [2,8]  63.5,3.16 270 top
U$2  [2,8]  147.32,3.16 270 top
U$3  [2,8]  147.32,125.08 270 top
U$4  [2,8]  63.5,125.08 270 top
U$5  [3,6]  8.89,71.74 0 top
U$6  [3,6]  46.99,71.74 0 top

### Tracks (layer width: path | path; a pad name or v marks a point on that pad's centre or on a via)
A1  (via drill 0.61)
  Top 0.254: v66.04,106.03 66.04,86.35 67.31,85.08 v67.31,33.64 67.31,10.14 71.12,6.33 IN1-2.1 | v78.11,33.64 80.65,31.1 SV1.10
  Bottom 0.254: v66.04,106.03 69.22,109.21 IC1.3 | v67.31,33.64 v78.11,33.64
B1  (via drill 0.61)
  Top 0.254: v72.39,27.29 72.39,7.6 73.66,6.33 IN1-2.3
  Bottom 0.254: 71.75,27.29 62.87,27.29 62.87,96.51 68.58,102.22 IC1.6 | 71.75,27.29 72.39,27.92 72.39,29.2 73.03,29.83 74.3,29.83 75.56,31.1 SV1.6 | v72.39,27.29 71.75,27.29
C1
  Top 0.254: SV1.1 71.75,28.56 73.03,28.56 SV1.3 73.66,27.92 74.93,26.65 74.93,7.6 76.2,6.33 IN1-2.5 | IC1.8 76.84,99.05 76.2,98.41 76.2,86.35 74.93,85.08 74.93,30.46 76.2,29.2 SV1.5 76.84,28.56 78.11,28.56 SV1.7 79.38,28.56 80.65,28.56 SV1.9 | SV1.11 84.45,28.56 85.72,28.56 SV1.13 87,28.56 88.27,28.56 SV1.15 89.53,28.56 90.81,28.56 SV1.17 92.08,28.56 93.34,28.56 SV1.19 94.62,28.56 95.89,28.56 SV1.21 97.16,28.56 98.43,28.56 SV1.23 | SV1.25 102.23,28.56 103.5,28.56 SV1.27 104.78,28.56 106.05,28.56 SV1.29 107.31,28.56 108.59,28.56 SV1.31 109.86,28.56 111.12,28.56 SV1.33
  Bottom 0.254: SV1.11 83.19,28.56 81.92,28.56 SV1.9 | SV1.25 100.97,28.56 99.69,28.56 SV1.23 | SV1.3 74.3,28.56 75.56,28.56 SV1.5
D1
  Bottom 0.254: 68.58,26.02 75.56,26.02 77.47,27.92 77.47,31.1 78.11,31.1 SV1.8 | 68.58,26.02 62.23,26.02 62.23,97.14 68.58,103.49 72.39,103.49 76.2,107.3 IC1.11 | 68.58,26.02 78.11,16.49 80.01,16.49 80.01,7.6 78.74,6.33 IN1-2.7
D2  (via drill 0.61)
  Top 0.254: v116.84,20.94 118.11,22.21 118.11,99.68 120.02,101.59 IC3.6
  Bottom 0.254: v116.84,20.94 112.4,20.94 111.12,19.67 | 111.12,19.67 109.86,18.4 SV2.6 | 111.12,19.67 97.79,19.67 97.79,7.6 99.06,6.33 IN3-4.3
E1  (via drill 0.61)
  Top 0.254: IC2.3 81.92,109.21 80.65,107.94 80.65,97.14 81.28,96.51 81.28,86.35 82.55,85.08 82.55,33.01 83.82,31.73 SV1.12 | v69.22,32.37 69.22,10.78 71.12,8.88 IN1-2.2
  Bottom 0.254: v69.22,32.37 81.92,32.37 83.19,31.1 SV1.12
E2  (via drill 0.61)
  Top 0.254: v116.2,95.87 113.66,93.33 113.66,46.34 113.03,45.7 113.03,26.65 | 113.03,26.65 113.03,20.3 111.76,19.04 SV2.8 | 113.03,26.65 105.41,19.04 105.41,15.22 102.87,12.68 102.87,7.6 101.6,6.33 IN3-4.5
  Bottom 0.254: v116.2,95.87 135.25,95.87 135.25,100.32 134.62,100.95 130.81,100.95 129.54,99.68 IC3.8
F1  (via drill 0.61)
  Top 0.254: IC2.6 83.19,101.59 86.36,98.41 86.36,86.35 85.09,85.08 85.09,33.01 86.36,31.73 SV1.14 | v77.47,12.68 v77.47,25.38
  Bottom 0.254: v77.47,12.68 73.66,8.88 IN1-2.4 | v77.47,25.38 80.01,27.92 80.01,29.83 84.45,29.83 85.72,31.1 SV1.14
F2
  Top 0.254: IC3.11 128.91,106.67 130.18,105.4 130.18,104.12 129.54,103.49 117.47,103.49 117.47,47.61 115.57,45.7 115.57,20.94 114.3,19.67 114.3,19.04 SV2.10 114.3,17.77 113.03,16.49 113.03,15.22 110.49,12.68 110.49,4.43 106.05,4.43 104.78,5.7 IN3-4.7
GND
  Top 0.508: SV2.7 111.12,15.86 109.86,15.86 SV2.5 | SV2.15 122.56,15.86 123.83,15.86 SV2.17 125.09,15.86 126.36,15.86 SV2.19 | SV2.25 133.99,15.86 132.72,15.86 SV2.23 | SV2.29 139.06,15.86 137.8,15.86 SV2.27 | SV2.33 144.14,15.86 142.88,15.86 SV2.31 | BYP7.2 125.09,76.82 125.09,60.95 123.83,59.68 IC7.7 123.19,58.41 123.19,34.91 121.92,33.64 T1GND.1 121.28,31.73 121.28,19.67 120.65,19.04 120.65,17.77 119.38,16.49 SV2.13 | IC4.7 133.99,99.05 134.62,98.41 134.62,92.7 BYP10.2 134.62,91.43 135.89,91.43 | 135.89,91.43 139.06,91.43 JP2.1 | IC1.7 70.48,100.32 71.75,101.59 71.75,117.46 BYP1.2 | 135.89,91.43 135.89,78.73 137.16,77.46 BYP8.2
  Bottom 0.508: SV2.1 104.78,15.86 106.05,15.86 SV2.3 107.31,15.86 108.59,15.86 SV2.5 | SV2.7 112.4,15.86 113.66,15.86 SV2.9 114.94,15.86 116.2,15.86 SV2.11 117.47,15.86 118.75,15.86 SV2.13 120.02,15.86 121.28,15.86 SV2.15 | SV2.19 127.64,15.86 128.91,15.86 SV2.21 130.18,15.86 131.44,15.86 SV2.23 | SV2.27 136.53,15.86 135.25,15.86 SV2.25 | SV2.31 141.61,15.86 140.34,15.86 SV2.29 | IC8.7 134.62,59.04 132.08,56.5 127,56.5 124.46,59.04 IC7.7 | BYP8.2 136.53,76.82 135.25,78.09 126.36,78.09 125.09,76.82 BYP7.2 | CORE-IO.11 78.11,81.9 76.2,83.81 CORE-IO.10 76.2,85.08 76.2,98.41 | 80.01,98.41 81.28,99.68 IC2.7 | 76.2,98.41 72.39,98.41 71.12,99.68 IC1.7 | 80.01,98.41 76.2,98.41 | 92.71,98.41 93.98,99.68 IC5.7 | 92.71,98.41 80.01,98.41 | 105.41,98.41 106.68,99.68 IC6.7 | 105.41,98.41 92.71,98.41 | 118.11,98.41 119.38,99.68 IC3.7 | 118.11,98.41 105.41,98.41 | 81.92,118.73 83.19,117.46 BYP2.2 | 81.92,118.73 73.03,118.73 71.75,117.46 BYP1.2 | 94.62,118.73 95.89,117.46 BYP3.2 | 81.92,118.73 94.62,118.73 | 107.31,118.73 108.59,117.46 BYP4.2 | 94.62,118.73 107.31,118.73 | 120.02,118.73 121.28,117.46 BYP5.2 | 107.31,118.73 120.02,118.73 | 120.02,118.73 132.72,118.73 133.99,117.46 BYP6.2 | 118.11,98.41 130.81,98.41 132.08,99.68 IC4.7
H1  (via drill 0.61)
  Top 0.254: IC2.8 90.81,99.05 91.44,98.41 91.44,34.27 88.9,31.73 SV1.16 | v79.38,23.48 79.38,12.05 76.2,8.88 IN1-2.6
  Bottom 0.254: v79.38,23.48 83.19,27.29 87,27.29 87.63,27.92 87.63,31.1 88.27,31.1 SV1.16
H2  (via drill 0.61)
  Top 0.254: v118.11,20.94 118.11,20.3 116.84,19.04 SV2.12
  Bottom 0.254: 110.49,22.21 110.49,20.3 97.16,20.3 96.52,19.67 96.52,8.88 IN3-4.2 | 110.49,22.21 110.49,85.08 120.65,95.23 135.89,95.23 135.89,97.14 139.7,100.95 142.88,100.95 142.88,102.86 142.24,103.49 139.7,103.49 133.99,109.21 IC4.3 | v118.11,20.94 116.84,22.21 110.49,22.21
J1
  Top 0.254: 87.63,30.46 87.63,85.08 88.9,86.35 88.9,96.51 88.27,97.14 88.27,105.4 89.53,106.67 IC2.11 | 87.63,30.46 88.27,29.83 93.34,29.83 93.34,31.1 SV1.20 | 87.63,30.46 87.63,29.83 83.19,29.83 82.55,29.2 82.55,27.92 80.65,26.02 80.65,10.78 78.74,8.88 IN1-2.8
J2  (via drill 0.61)
  Top 0.254: IC4.6 132.72,101.59 120.65,89.52 120.65,20.3 119.38,19.04 SV2.14 119.38,17.77 118.11,16.49 118.11,12.05 v116.84,10.78
  Bottom 0.254: v116.84,10.78 102.23,10.78 99.69,8.24 IN3-4.4
K1  (via drill 0.61)
  Top 0.254: IC5.3 94.62,109.21 93.34,107.94 93.34,97.14 93.98,96.51 93.98,78.09 92.08,76.19 92.08,31.1 SV1.18 | v82.55,20.3 82.55,7.6 81.28,6.33 IN1-2.9
  Bottom 0.254: v82.55,20.3 90.17,27.92 90.17,31.1 90.81,31.1 SV1.18
K2  (via drill 0.61)
  Top 0.254: v125.73,24.75 121.92,20.94 121.92,19.04 SV2.16 121.92,17.77 120.65,16.49 120.65,13.32 v116.84,9.51
  Bottom 0.254: v125.73,24.75 145.42,24.75 145.42,91.43 141.61,95.23 141.61,99.05 IC4.8 | v116.84,9.51 103.5,9.51 102.23,8.24 IN3-4.6
L1  (via drill 0.61)
  Top 0.254: IC5.6 95.89,101.59 97.16,100.32 97.16,97.14 96.52,96.51 96.52,78.09 97.79,76.82 97.79,33.01 99.06,31.73 SV1.24 | v90.81,6.97 101.6,17.77 v101.6,26.65
  Bottom 0.254: v90.81,6.97 85.72,6.97 84.45,5.7 IN1-2.11 | v101.6,26.65 102.87,27.92 102.87,32.37 100.97,32.37 99.69,31.1 SV1.24
L2  (via drill 0.61)
  Top 0.254: v125.73,23.48 124.46,22.21 124.46,19.04 SV2.18
  Bottom 0.254: 146.05,23.48 v125.73,23.48 | 146.05,23.48 147.95,23.48 147.95,100.32 141.61,106.67 IC4.11 | 146.05,23.48 146.05,10.14 138.43,2.53 105.41,2.53 105.41,6.33 104.14,7.6 IN3-4.8
M1  (via drill 0.61)
  Top 0.254: v106.05,100.95 106.05,97.14 106.68,96.51 106.68,78.09 105.41,76.82 105.41,33.01 104.14,31.73 SV1.28 | v87.63,17.13 87.63,7.6 86.36,6.33 IN1-2.13
  Bottom 0.254: v106.05,100.95 105.41,100.95 104.14,99.68 IC5.8 | v87.63,17.13 95.25,24.75 102.23,24.75 105.41,27.92 105.41,30.46 104.14,30.46 SV1.28
M2  (via drill 0.61)
  Top 0.254: v126.36,29.2 127,28.56 127,19.04 SV2.20 | v107.95,17.13 107.95,7.6 106.68,6.33 IN3-4.9
  Bottom 0.254: v126.36,29.2 120.65,29.2 120.65,68.57 121.28,68.57 121.92,69.2 IC7.3 | v107.95,17.13 125.09,17.13 126.36,18.4 SV2.20
N1  (via drill 0.61)
  Top 0.254: IC5.11 102.23,106.67 99.06,103.49 99.06,78.09 100.33,76.82 100.33,30.46 99.69,29.83 96.52,29.83 96.52,30.46 SV1.22 | v93.34,26.02 93.34,10.78 88.9,6.33 IN1-2.15
  Bottom 0.254: v93.34,26.02 95.25,27.92 95.25,31.1 95.89,31.1 SV1.22
N2  (via drill 0.61)
  Top 0.254: v127.64,57.77 128.27,57.13 128.27,20.3 | 128.27,20.3 129.54,19.04 SV2.22 | v120.02,6.97 128.27,6.97 128.27,20.3
  Bottom 0.254: v127.64,57.77 127,57.77 123.83,60.95 IC7.6 | v120.02,6.97 111.12,6.97 109.86,5.7 IN3-4.11
N$26
  Bottom 0.254: A5.L1 36.2,104.12 36.83,103.49 47.62,103.49 48.26,104.12 A9.L1
N$33
  Bottom 0.254: A5.L2 29.85,105.4 30.48,106.03 41.28,106.03 41.91,105.4 A9.L2
N$34
  Bottom 0.254: A5.M1 39.37,100.95 40.01,100.32 50.8,100.32 51.44,100.95 A9.M1
N$35
  Bottom 0.254: A5.M2 33.02,102.22 33.66,102.86 44.45,102.86 45.09,102.22 A9.M2
N$36
  Bottom 0.254: A5.N1 36.2,97.78 36.83,97.14 47.62,97.14 48.26,97.78 A9.N1
N$49
  Bottom 0.254: A5.N2 29.85,99.05 30.48,99.68 41.28,99.68 41.91,99.05 A9.N2
N$50
  Bottom 0.254: A5.P1 39.37,94.6 40.01,93.97 50.8,93.97 51.44,94.6 A9.P1
N$51
  Bottom 0.254: A5.P2 33.02,95.87 33.66,96.51 44.45,96.51 45.09,95.87 A9.P2
N$52
  Bottom 0.254: A5.R1 36.2,91.43 36.83,90.79 47.62,90.79 48.26,91.43 A9.R1
N$53
  Bottom 0.254: IC1.1 69.85,115.56 69.85,122.54 70.48,122.54 OUT1-2.1
N$54
  Bottom 0.254: IC1.4 70.48,107.94 71.75,109.21 71.75,113.65 68.58,113.65 67.95,114.29 67.95,123.81 71.75,123.81 73.03,122.54 OUT1-2.3
N$55
  Top 0.254: IC1.10 76.84,105.4 73.66,108.57 73.66,119.37 76.2,121.91 OUT1-2.5
N$56
  Top 0.254: IC1.13 76.84,113.02 74.93,114.92 74.93,118.1 78.74,121.91 OUT1-2.7
N$57
  Top 0.254: IC1.2 69.22,113.02 67.95,114.29 67.95,121.27 71.12,124.45 OUT1-2.2
N$58
  Top 0.254: IC1.5 69.22,105.4 67.31,107.3 67.31,123.18 70.48,126.35 73.66,126.35 73.66,125.72 OUT1-2.4
N$59
  Top 0.254: IC1.9 76.84,102.86 73.03,106.67 73.03,120 74.93,121.91 74.93,123.18 76.2,124.45 OUT1-2.6
N$60
  Top 0.254: IC1.12 76.84,110.48 74.3,113.02 74.3,118.73 77.47,121.91 77.47,123.18 78.74,124.45 OUT1-2.8
N$61  (via drill 0.61)
  Top 0.254: v124.46,109.21 124.46,121.91 OUT5-6.3
  Bottom 0.254: v124.46,109.21 123.83,109.21 121.92,107.3 IC3.4
N$62  (via drill 0.61)
  Top 0.254: v87,107.94 86.36,108.57 86.36,121.91 OUT1-2.13
  Bottom 0.254: v87,107.94 89.53,105.4 IC2.10
N$63
  Top 0.254: IC2.4 83.19,107.94 85.09,109.84 85.09,120.64 83.82,121.91 OUT1-2.11
N$64
  Top 0.254: IC2.1 81.92,115.56 81.28,116.19 81.28,121.91 OUT1-2.9
N$65
  Top 0.254: IC2.2 83.19,113.02 84.45,114.29 84.45,115.56 83.82,116.19 82.55,116.19 82.55,123.18 81.28,124.45 OUT1-2.10
N$66
  Top 0.254: IC2.5 83.19,105.4 85.72,107.94 85.72,121.27 85.09,121.91 85.09,123.18 83.82,124.45 OUT1-2.12
N$67  (via drill 0.61)
  Top 0.254: v80.65,113.65 80.01,114.29 80.01,125.72 80.65,126.35 86.36,126.35 86.36,125.72 OUT1-2.14
  Bottom 0.254: v80.65,113.65 84.45,113.65 84.45,107.94 89.53,102.86 IC2.9
N$68
  Top 0.254: IC2.12 90.81,110.48 92.71,112.38 92.71,120.64 88.9,124.45 OUT1-2.16
N$69
  Bottom 0.254: A5.R2 29.85,92.7 30.48,93.33 41.28,93.33 41.91,92.7 A9.R2
N$70
  Bottom 0.254: A5.S1 39.37,88.25 40.01,87.62 50.8,87.62 51.44,88.25 A9.S1
N$71
  Bottom 0.254: A5.S2 33.02,89.52 33.66,90.16 44.45,90.16 45.09,89.52 A9.S2
N$72
  Bottom 0.254: A5.T1 36.2,85.08 36.83,84.44 47.62,84.44 48.26,85.08 A9.T1
N$73
  Bottom 0.254: A5.T2 29.85,86.35 30.48,86.98 41.28,86.98 41.91,86.35 A9.T2
N$74
  Bottom 0.254: A5.U1 39.37,81.9 40.01,81.27 50.8,81.27 51.44,81.9 A9.U1
N$75
  Bottom 0.254: A5.U2 33.02,83.17 33.66,83.81 44.45,83.81 45.09,83.17 A9.U2
N$76
  Bottom 0.254: A5.V1 36.2,78.73 36.83,78.09 47.62,78.09 48.26,78.73 A9.V1
N$81
  Bottom 0.254: A5.V2 29.85,80 30.48,80.63 41.28,80.63 41.91,80 A9.V2
N$82
  Bottom 0.254: A5.A1 39.37,132.7 40.01,132.06 50.8,132.06 51.44,132.7 A9.A1
N$83
  Bottom 0.254: A5.A2 33.02,133.97 33.66,134.6 44.45,134.6 45.09,133.97 A9.A2
N$84
  Bottom 0.254: A5.B1 36.2,129.53 36.83,128.89 47.62,128.89 48.26,129.53 A9.B1
N$85
  Bottom 0.254: A5.B2 29.85,130.79 30.48,131.43 41.28,131.43 41.91,130.79 A9.B2
N$86
  Bottom 0.254: A5.C1 39.37,126.35 40.01,125.72 50.8,125.72 51.44,126.35 A9.C1
N$87
  Bottom 0.254: A5.C2 33.02,127.62 33.66,128.25 44.45,128.25 45.09,127.62 A9.C2
N$88
  Bottom 0.254: A5.D1 36.2,123.18 36.83,122.54 47.62,122.54 48.26,123.18 A9.D1
N$89
  Bottom 0.254: A5.D2 29.85,124.45 30.48,125.08 41.28,125.08 41.91,124.45 A9.D2
N$90
  Bottom 0.254: A5.E1 39.37,120 40.01,119.37 50.8,119.37 51.44,120 A9.E1
N$91
  Bottom 0.254: A5.E2 33.02,121.27 33.66,121.91 44.45,121.91 45.09,121.27 A9.E2
N$92
  Bottom 0.254: A5.F1 36.2,116.83 36.83,116.19 47.62,116.19 48.26,116.83 A9.F1
N$93
  Bottom 0.254: A5.F2 29.85,118.1 30.48,118.73 41.28,118.73 41.91,118.1 A9.F2
N$95
  Bottom 0.254: A5.H1 39.37,113.65 40.01,113.02 50.8,113.02 51.44,113.65 A9.H1
N$96
  Bottom 0.254: A5.H2 33.02,114.92 33.66,115.56 44.45,115.56 45.09,114.92 A9.H2
N$97
  Bottom 0.254: A5.J1 36.2,110.48 36.83,109.84 47.62,109.84 48.26,110.48 A9.J1
N$98
  Bottom 0.254: A5.J2 29.85,111.75 30.48,112.38 41.28,112.38 41.91,111.75 A9.J2
N$99
  Bottom 0.254: A5.K1 39.37,107.3 40.01,106.67 50.8,106.67 51.44,107.3 A9.K1
N$100
  Bottom 0.254: A5.K2 33.02,108.57 33.66,109.21 44.45,109.21 45.09,108.57 A9.K2
N$113
  Bottom 0.254: A6.L1 10.8,104.12 11.43,103.49 22.23,103.49 22.86,104.12 A7.L1
N$114
  Bottom 0.254: A6.L2 4.45,105.4 5.08,106.03 15.88,106.03 16.51,105.4 A7.L2
N$115
  Bottom 0.254: A6.M1 13.97,100.95 14.61,100.32 25.4,100.32 26.04,100.95 A7.M1
N$116
  Bottom 0.254: A6.M2 7.62,102.22 8.26,102.86 19.05,102.86 19.69,102.22 A7.M2
N$117
  Bottom 0.254: A6.N1 10.8,97.78 11.43,97.14 22.23,97.14 22.86,97.78 A7.N1
N$118
  Bottom 0.254: A6.N2 4.45,99.05 5.08,99.68 15.88,99.68 16.51,99.05 A7.N2
N$119
  Bottom 0.254: A6.P1 13.97,94.6 14.61,93.97 25.4,93.97 26.04,94.6 A7.P1
N$120
  Bottom 0.254: A6.P2 7.62,95.87 8.26,96.51 19.05,96.51 19.69,95.87 A7.P2
N$121
  Bottom 0.254: A6.R1 10.8,91.43 11.43,90.79 22.23,90.79 22.86,91.43 A7.R1
N$122
  Bottom 0.254: A6.R2 4.45,92.7 5.08,93.33 15.88,93.33 16.51,92.7 A7.R2
N$123
  Bottom 0.254: A6.S1 13.97,88.25 14.61,87.62 25.4,87.62 26.04,88.25 A7.S1
N$137
  Bottom 0.254: A6.S2 7.62,89.52 8.26,90.16 19.05,90.16 19.69,89.52 A7.S2
N$138
  Top 0.254: IC3.13 128.91,113.02 130.18,114.29 130.18,122.54 OUT5-6.7
N$139
  Top 0.254: IC2.13 90.81,113.02 92.08,114.29 92.08,118.73 88.9,121.91 OUT1-2.15
N$140
  Top 0.254: IC3.2 120.02,113.02 118.75,114.29 118.75,121.27 121.92,124.45 OUT5-6.2
N$141
  Top 0.254: IC3.5 121.92,104.76 123.19,104.76 123.19,123.18 124.46,124.45 OUT5-6.4
N$142
  Top 0.254: IC3.9 129.54,102.22 131.44,102.22 131.44,102.86 132.08,103.49 136.53,103.49 136.53,121.27 135.89,121.91 135.89,125.72 135.25,126.35 127,126.35 127,125.72 OUT5-6.6
N$143
  Top 0.254: IC3.12 127,109.84 125.09,109.84 125.09,121.27 125.73,121.91 125.73,123.18 126.36,123.81 128.91,123.81 128.91,125.08 OUT5-6.8
N$144
  Top 0.254: IC4.10 140.34,105.4 137.16,108.57 137.16,121.91 OUT5-6.13
N$145
  Top 0.254: IC4.4 133.99,107.94 135.89,109.84 135.89,120.64 134.62,121.91 OUT5-6.11
N$146
  Top 0.254: IC4.1 132.72,115.56 132.08,116.19 132.08,121.91 OUT5-6.9
N$147
  Top 0.254: IC4.2 132.72,113.02 130.81,114.92 130.81,123.18 132.08,124.45 OUT5-6.10
N$148
  Bottom 0.254: IC4.9 139.7,102.22 135.89,106.03 132.08,106.03 131.44,106.67 131.44,113.65 137.16,113.65 139.7,116.19 140.34,116.19 140.97,116.83 140.97,123.81 139.06,123.81 137.8,125.08 OUT5-6.14
N$149
  Bottom 0.254: IC4.12 141.61,110.48 142.88,111.75 142.88,124.45 139.7,124.45 OUT5-6.16
N$150
  Top 0.254: IC3.1 120.65,115.56 120.65,120.64 121.92,121.91 OUT5-6.1
N$151
  Top 0.254: IC3.10 127.64,105.4 126.36,106.67 126.36,107.94 127,108.57 130.18,108.57 130.18,110.48 129.54,111.11 125.73,111.11 125.73,120.64 127,121.91 OUT5-6.5
N$152
  Top 0.254: IC4.5 132.72,105.4 131.44,106.67 131.44,110.48 132.08,111.11 135.25,111.11 135.25,115.56 134.62,116.19 133.35,116.19 133.35,123.18 134.62,124.45 OUT5-6.12
N$153
  Top 0.254: IC4.13 140.34,113.02 138.43,114.92 138.43,120.64 139.7,121.91 OUT5-6.15
N$154  (via drill 0.61)
  Top 0.254: v99.06,109.21 99.06,121.91 OUT3-4.3
  Bottom 0.254: v99.06,109.21 98.43,109.21 96.52,107.3 IC5.4
N$155
  Top 0.254: IC5.13 103.5,113.02 104.78,114.29 104.78,122.54 OUT3-4.7
N$156
  Top 0.254: IC5.2 94.62,113.02 93.34,114.29 93.34,121.27 96.52,124.45 OUT3-4.2
N$157
  Top 0.254: IC5.5 95.89,105.4 97.16,106.67 97.16,110.48 96.52,111.11 92.71,111.11 92.71,109.84 91.44,108.57 87.63,108.57 87.63,125.72 88.27,126.35 99.06,126.35 99.06,125.72 OUT3-4.4
N$158
  Top 0.254: IC5.9 103.5,102.86 104.78,104.12 104.78,110.48 104.14,111.11 100.33,111.11 100.33,119.37 102.87,121.91 102.87,123.18 101.6,124.45 OUT3-4.6
N$159
  Top 0.254: IC5.12 101.6,109.84 99.69,109.84 99.69,121.27 100.33,121.91 100.33,125.72 100.97,126.35 104.14,126.35 104.14,125.72 OUT3-4.8
N$160
  Top 0.254: IC6.10 116.84,104.76 118.75,104.76 118.75,105.4 119.38,106.03 122.56,106.03 122.56,110.48 121.92,111.11 118.11,111.11 118.11,109.84 116.84,108.57 111.76,108.57 111.76,121.91 OUT3-4.13
N$161
  Top 0.254: IC6.4 108.59,107.94 110.49,109.84 110.49,120.64 109.22,121.91 OUT3-4.11
N$162
  Top 0.254: IC6.1 107.31,115.56 106.68,116.19 106.68,121.91 OUT3-4.9
N$163
  Top 0.254: IC6.2 107.31,113.02 105.41,114.92 105.41,123.18 106.68,124.45 OUT3-4.10
N$164  (via drill 0.61)
  Top 0.254: v113.66,111.11 112.4,112.38 112.4,121.27 113.03,121.91 113.03,123.18 111.76,124.45 OUT3-4.14
  Bottom 0.254: v113.66,111.11 117.47,111.11 117.47,104.12 116.2,102.86 IC6.9
N$165
  Top 0.254: IC6.12 116.2,110.48 117.47,111.75 117.47,121.27 114.3,124.45 OUT3-4.16
N$166
  Top 0.254: IC5.1 95.25,115.56 95.25,120.64 96.52,121.91 OUT3-4.1
N$167  (via drill 0.61)
  Top 0.254: v99.06,107.94 97.79,109.21 v97.79,120
  Bottom 0.254: v99.06,107.94 99.69,107.94 102.23,105.4 IC5.10 | v97.79,120 99.06,121.27 99.69,121.27 100.97,122.54 OUT3-4.5
N$168
  Top 0.254: IC6.5 108.59,105.4 111.12,107.94 111.12,121.27 110.49,121.91 110.49,123.18 109.22,124.45 OUT3-4.12
N$169
  Top 0.254: IC6.13 114.94,113.02 113.03,114.92 113.03,120.64 114.3,121.91 OUT3-4.15
N$170  (via drill 0.61)
  Top 0.254: v127.64,69.84 127.64,81.9 OUT7-8.3
  Bottom 0.254: v127.64,69.84 124.46,66.66 IC7.4
N$171
  Top 0.254: IC7.13 131.44,72.38 132.72,73.65 132.72,81.9 OUT7-8.7
N$172  (via drill 0.61)
  Top 0.254: v126.36,74.28 125.73,74.92 125.73,82.54 124.46,83.81 OUT7-8.2
  Bottom 0.254: v126.36,74.28 125.73,74.28 123.83,72.38 IC7.2
N$173
  Top 0.254: IC7.5 122.56,64.76 121.28,66.03 121.28,83.17 123.83,85.71 127,85.71 127,85.08 OUT7-8.4
N$174
  Bottom 0.254: IC7.9 129.54,61.58 125.73,65.39 121.92,65.39 121.28,66.03 121.28,67.93 124.46,67.93 125.09,68.57 125.09,70.47 121.92,70.47 121.28,71.11 121.28,83.17 127.64,83.17 128.91,84.44 OUT7-8.6
N$175
  Top 0.254: IC7.12 130.18,69.84 128.27,71.74 128.27,78.73 130.81,81.27 130.81,82.54 132.08,83.81 OUT7-8.8
N$176
  Top 0.254: IC8.10 142.88,64.76 141.61,66.03 141.61,67.3 142.24,67.93 146.05,67.93 146.05,82.54 142.88,85.71 138.43,85.71 138.43,83.81 139.7,82.54 OUT7-8.13
N$177
  Top 0.254: IC8.4 136.53,67.3 138.43,69.2 138.43,80 137.16,81.27 OUT7-8.11
N$178
  Top 0.254: IC8.1 135.25,74.92 134.62,75.55 134.62,81.27 OUT7-8.9
N$179
  Top 0.254: IC8.2 135.25,72.38 133.35,74.28 133.35,82.54 134.62,83.81 OUT7-8.10
N$180
  Top 0.254: IC8.9 142.88,62.21 140.34,64.76 140.34,80.63 140.97,81.27 140.97,82.54 139.7,83.81 OUT7-8.14
N$181
  Top 0.254: IC8.12 144.14,69.84 145.42,71.11 145.42,80.63 142.24,83.81 OUT7-8.16
N$182
  Bottom 0.254: IC7.1 122.56,74.92 122.56,81.9 123.83,81.9 OUT7-8.1
N$183
  Bottom 0.254: IC7.10 130.18,64.76 128.91,66.03 128.91,75.55 123.83,75.55 123.19,76.19 123.19,80.63 127.64,80.63 128.91,81.9 OUT7-8.5
N$184
  Top 0.254: IC8.5 136.53,64.76 139.06,67.3 139.06,80.63 138.43,81.27 138.43,82.54 137.16,83.81 OUT7-8.12
N$185
  Top 0.254: IC8.13 142.88,72.38 140.97,74.28 140.97,80 142.24,81.27 OUT7-8.15
N$186
  Bottom 0.254: A6.T1 10.8,85.08 11.43,84.44 22.23,84.44 22.86,85.08 A7.T1
N$187
  Bottom 0.254: A6.T2 4.45,86.35 5.08,86.98 15.88,86.98 16.51,86.35 A7.T2
N$188
  Bottom 0.254: A6.U1 13.97,81.9 14.61,81.27 25.4,81.27 26.04,81.9 A7.U1
N$189
  Bottom 0.254: A6.U2 7.62,83.17 8.26,83.81 19.05,83.81 19.69,83.17 A7.U2
N$190
  Bottom 0.254: A6.V1 10.8,78.73 11.43,78.09 22.23,78.09 22.86,78.73 A7.V1
N$191
  Bottom 0.254: A6.V2 4.45,80 5.08,80.63 15.88,80.63 16.51,80 A7.V2
N$192
  Bottom 0.254: A6.A1 13.97,132.7 14.61,132.06 25.4,132.06 26.04,132.7 A7.A1
N$193
  Bottom 0.254: A6.A2 7.62,133.97 8.26,134.6 19.05,134.6 19.69,133.97 A7.A2
N$194
  Bottom 0.254: A6.B1 10.8,129.53 11.43,128.89 22.23,128.89 22.86,129.53 A7.B1
N$195
  Bottom 0.254: A6.B2 4.45,130.79 5.08,131.43 15.88,131.43 16.51,130.79 A7.B2
N$196
  Bottom 0.254: A6.C1 13.97,126.35 14.61,125.72 25.4,125.72 26.04,126.35 A7.C1
N$197
  Bottom 0.254: A6.C2 7.62,127.62 8.26,128.25 19.05,128.25 19.69,127.62 A7.C2
N$198
  Bottom 0.254: A6.D1 10.8,123.18 11.43,122.54 22.23,122.54 22.86,123.18 A7.D1
N$199
  Bottom 0.254: A6.D2 4.45,124.45 5.08,125.08 15.88,125.08 16.51,124.45 A7.D2
N$200
  Bottom 0.254: A6.E1 13.97,120 14.61,119.37 25.4,119.37 26.04,120 A7.E1
N$201
  Bottom 0.254: A6.E2 7.62,121.27 8.26,121.91 19.05,121.91 19.69,121.27 A7.E2
N$202
  Bottom 0.254: A6.F1 10.8,116.83 11.43,116.19 22.23,116.19 22.86,116.83 A7.F1
N$203
  Bottom 0.254: A6.F2 4.45,118.1 5.08,118.73 15.88,118.73 16.51,118.1 A7.F2
N$204
  Bottom 0.254: A6.H1 13.97,113.65 14.61,113.02 25.4,113.02 26.04,113.65 A7.H1
N$205
  Bottom 0.254: A6.H2 7.62,114.92 8.26,115.56 19.05,115.56 19.69,114.92 A7.H2
N$206
  Bottom 0.254: A6.J1 10.8,110.48 11.43,109.84 22.23,109.84 22.86,110.48 A7.J1
N$207
  Bottom 0.254: A6.J2 4.45,111.75 5.08,112.38 15.88,112.38 16.51,111.75 A7.J2
N$208
  Bottom 0.254: A6.K1 13.97,107.3 14.61,106.67 25.4,106.67 26.04,107.3 A7.K1
N$209
  Bottom 0.254: A6.K2 7.62,108.57 8.26,109.21 19.05,109.21 19.69,108.57 A7.K2
N$210
  Bottom 0.254: A8.L1 10.8,34.27 11.43,33.64 22.23,33.64 22.86,34.27 A10.L1
N$211
  Bottom 0.254: A8.L2 4.45,35.55 5.08,36.18 15.88,36.18 16.51,35.55 A10.L2
N$212
  Bottom 0.254: A8.M1 13.97,31.1 14.61,30.46 25.4,30.46 26.04,31.1 A10.M1
N$213
  Bottom 0.254: A8.M2 7.62,32.37 8.26,33.01 19.05,33.01 19.69,32.37 A10.M2
N$214
  Bottom 0.254: A8.N1 10.8,27.92 11.43,27.29 22.23,27.29 22.86,27.92 A10.N1
N$215
  Bottom 0.254: A8.N2 4.45,29.2 5.08,29.83 15.88,29.83 16.51,29.2 A10.N2
N$216
  Bottom 0.254: A8.P1 13.97,24.75 14.61,24.11 25.4,24.11 26.04,24.75 A10.P1
N$217
  Bottom 0.254: A8.P2 7.62,26.02 8.26,26.65 19.05,26.65 19.69,26.02 A10.P2
N$218
  Bottom 0.254: A8.R1 10.8,21.57 11.43,20.94 22.23,20.94 22.86,21.57 A10.R1
N$219
  Bottom 0.254: A8.R2 4.45,22.84 5.08,23.48 15.88,23.48 16.51,22.84 A10.R2
N$220
  Bottom 0.254: A8.S1 13.97,18.4 14.61,17.77 25.4,17.77 26.04,18.4 A10.S1
N$221
  Bottom 0.254: A8.S2 7.62,19.67 8.26,20.3 19.05,20.3 19.69,19.67 A10.S2
N$222
  Bottom 0.254: A8.T1 10.8,15.22 11.43,14.59 22.23,14.59 22.86,15.22 A10.T1
N$223
  Bottom 0.254: A8.T2 4.45,16.49 5.08,17.13 15.88,17.13 16.51,16.49 A10.T2
N$224
  Bottom 0.254: A8.U1 13.97,12.05 14.61,11.41 25.4,11.41 26.04,12.05 A10.U1
N$225
  Bottom 0.254: A8.U2 7.62,13.32 8.26,13.95 19.05,13.95 19.69,13.32 A10.U2
N$226
  Bottom 0.254: A8.V1 10.8,8.88 11.43,8.24 22.23,8.24 22.86,8.88 A10.V1
N$227
  Bottom 0.254: A8.V2 4.45,10.14 5.08,10.78 15.88,10.78 16.51,10.14 A10.V2
N$228
  Bottom 0.254: A8.A1 13.97,62.85 14.61,62.21 25.4,62.21 26.04,62.85 A10.A1
N$229
  Bottom 0.254: A8.A2 7.62,64.12 8.26,64.76 19.05,64.76 19.69,64.12 A10.A2
N$230
  Bottom 0.254: A8.B1 10.8,59.68 11.43,59.04 22.23,59.04 22.86,59.68 A10.B1
N$231
  Bottom 0.254: A8.B2 4.45,60.95 5.08,61.58 15.88,61.58 16.51,60.95 A10.B2
N$232
  Bottom 0.254: A8.C1 13.97,56.5 14.61,55.87 25.4,55.87 26.04,56.5 A10.C1
N$233
  Bottom 0.254: A8.C2 7.62,57.77 8.26,58.41 19.05,58.41 19.69,57.77 A10.C2
N$234
  Bottom 0.254: A8.D1 10.8,53.32 11.43,52.69 22.23,52.69 22.86,53.32 A10.D1
N$235
  Bottom 0.254: A8.D2 4.45,54.59 5.08,55.23 15.88,55.23 16.51,54.59 A10.D2
N$236
  Bottom 0.254: A8.E1 13.97,50.15 14.61,49.52 25.4,49.52 26.04,50.15 A10.E1
N$237
  Bottom 0.254: A8.E2 7.62,51.42 8.26,52.05 19.05,52.05 19.69,51.42 A10.E2
N$238
  Bottom 0.254: A8.F1 10.8,46.98 11.43,46.34 22.23,46.34 22.86,46.98 A10.F1
N$239
  Bottom 0.254: A8.F2 4.45,48.24 5.08,48.88 15.88,48.88 16.51,48.24 A10.F2
N$240
  Bottom 0.254: A8.H1 13.97,43.8 14.61,43.16 25.4,43.16 26.04,43.8 A10.H1
N$241
  Bottom 0.254: A8.H2 7.62,45.07 8.26,45.7 19.05,45.7 19.69,45.07 A10.H2
N$242
  Bottom 0.254: A8.J1 10.8,40.62 11.43,39.99 22.23,39.99 22.86,40.62 A10.J1
N$243
  Bottom 0.254: A8.J2 4.45,41.89 5.08,42.53 15.88,42.53 16.51,41.89 A10.J2
N$244
  Bottom 0.254: A8.K1 13.97,37.45 14.61,36.81 25.4,36.81 26.04,37.45 A10.K1
N$245
  Bottom 0.254: A8.K2 7.62,38.72 8.26,39.35 19.05,39.35 19.69,38.72 A10.K2
N$246
  Bottom 0.254: A11.L1 36.2,34.27 36.83,33.64 47.62,33.64 48.26,34.27 A12.L1
N$247
  Bottom 0.254: A11.L2 29.85,35.55 30.48,36.18 41.28,36.18 41.91,35.55 A12.L2
N$248
  Bottom 0.254: A11.M1 39.37,31.1 40.01,30.46 50.8,30.46 51.44,31.1 A12.M1
N$249
  Bottom 0.254: A11.M2 33.02,32.37 33.66,33.01 44.45,33.01 45.09,32.37 A12.M2
N$250
  Bottom 0.254: A11.N1 36.2,27.92 36.83,27.29 47.62,27.29 48.26,27.92 A12.N1
N$251
  Bottom 0.254: A11.N2 29.85,29.2 30.48,29.83 41.28,29.83 41.91,29.2 A12.N2
N$252
  Bottom 0.254: A11.P1 39.37,24.75 40.01,24.11 50.8,24.11 51.44,24.75 A12.P1
N$253
  Bottom 0.254: A11.P2 33.02,26.02 33.66,26.65 44.45,26.65 45.09,26.02 A12.P2
N$254
  Bottom 0.254: A11.R1 36.2,21.57 36.83,20.94 47.62,20.94 48.26,21.57 A12.R1
N$255
  Bottom 0.254: A11.R2 29.85,22.84 30.48,23.48 41.28,23.48 41.91,22.84 A12.R2
N$256
  Bottom 0.254: A11.S1 39.37,18.4 40.01,17.77 50.8,17.77 51.44,18.4 A12.S1
N$257
  Bottom 0.254: A11.S2 33.02,19.67 33.66,20.3 44.45,20.3 45.09,19.67 A12.S2
N$258
  Bottom 0.254: A11.T1 36.2,15.22 36.83,14.59 47.62,14.59 48.26,15.22 A12.T1
N$259
  Bottom 0.254: A11.T2 29.85,16.49 30.48,17.13 41.28,17.13 41.91,16.49 A12.T2
N$260
  Bottom 0.254: A11.U1 39.37,12.05 40.01,11.41 50.8,11.41 51.44,12.05 A12.U1
N$261
  Bottom 0.254: A11.U2 33.02,13.32 33.66,13.95 44.45,13.95 45.09,13.32 A12.U2
N$262
  Bottom 0.254: A11.V1 36.2,8.88 36.83,8.24 47.62,8.24 48.26,8.88 A12.V1
N$263
  Bottom 0.254: A11.V2 29.85,10.14 30.48,10.78 41.28,10.78 41.91,10.14 A12.V2
N$264
  Bottom 0.254: A11.A1 39.37,62.85 40.01,62.21 50.8,62.21 51.44,62.85 A12.A1
N$265
  Bottom 0.254: A11.A2 33.02,64.12 33.66,64.76 44.45,64.76 45.09,64.12 A12.A2
N$266
  Bottom 0.254: A11.B1 36.2,59.68 36.83,59.04 47.62,59.04 48.26,59.68 A12.B1
N$267
  Bottom 0.254: A11.B2 29.85,60.95 30.48,61.58 41.28,61.58 41.91,60.95 A12.B2
N$268
  Bottom 0.254: A11.C1 39.37,56.5 40.01,55.87 50.8,55.87 51.44,56.5 A12.C1
N$269
  Bottom 0.254: A11.C2 33.02,57.77 33.66,58.41 44.45,58.41 45.09,57.77 A12.C2
N$270
  Bottom 0.254: A11.D1 36.2,53.32 36.83,52.69 47.62,52.69 48.26,53.32 A12.D1
N$271
  Bottom 0.254: A11.D2 29.85,54.59 30.48,55.23 41.28,55.23 41.91,54.59 A12.D2
N$272
  Bottom 0.254: A11.E1 39.37,50.15 40.01,49.52 50.8,49.52 51.44,50.15 A12.E1
N$273
  Bottom 0.254: A11.E2 33.02,51.42 33.66,52.05 44.45,52.05 45.09,51.42 A12.E2
N$274
  Bottom 0.254: A11.F1 36.2,46.98 36.83,46.34 47.62,46.34 48.26,46.98 A12.F1
N$275
  Bottom 0.254: A11.F2 29.85,48.24 30.48,48.88 41.28,48.88 41.91,48.24 A12.F2
N$276
  Bottom 0.254: A11.H1 39.37,43.8 40.01,43.16 50.8,43.16 51.44,43.8 A12.H1
N$277
  Bottom 0.254: A11.H2 33.02,45.07 33.66,45.7 44.45,45.7 45.09,45.07 A12.H2
N$278
  Bottom 0.254: A11.J1 36.2,40.62 36.83,39.99 47.62,39.99 48.26,40.62 A12.J1
N$279
  Bottom 0.254: A11.J2 29.85,41.89 30.48,42.53 41.28,42.53 41.91,41.89 A12.J2
N$280
  Bottom 0.254: A11.K1 39.37,37.45 40.01,36.81 50.8,36.81 51.44,37.45 A12.K1
N$281
  Bottom 0.254: A11.K2 33.02,38.72 33.66,39.35 44.45,39.35 45.09,38.72 A12.K2
P1
  Top 0.254: IC6.3 107.31,109.21 106.05,107.94 106.05,104.12 106.68,103.49 109.86,103.49 109.86,97.14 109.22,96.51 109.22,78.09 107.95,76.82 107.95,33.01 106.68,31.73 SV1.30 106.05,31.1 106.05,29.83 100.97,29.83 100.33,29.2 100.33,27.29 88.27,27.29 81.28,20.3 81.28,8.88 IN1-2.10
P2  (via drill 0.61)
  Top 0.254: 130.81,20.3 130.81,58.41 IC7.8 | 130.81,20.3 132.08,19.04 SV2.24 | v130.81,6.97 130.81,20.3
  Bottom 0.254: v130.81,6.97 121.28,6.97 118.75,4.43 113.66,4.43 112.4,5.7 IN3-4.13
R1  (via drill 0.61)
  Top 0.254: IC6.6 106.68,102.22 104.78,102.22 104.78,97.14 104.14,96.51 104.14,78.09 102.87,76.82 102.87,33.01 101.6,31.73 SV1.26 | v86.36,17.13 86.36,11.41 83.82,8.88 IN1-2.12
  Bottom 0.254: v86.36,17.13 96.52,27.29 97.16,27.29 97.79,27.92 97.79,29.83 99.69,29.83 100.97,31.1 SV1.26
R2  (via drill 0.61)
  Top 0.254: IC7.11 131.44,66.03 133.35,64.12 133.35,20.3 134.62,19.04 SV2.26 | v115.57,19.67 115.57,7.6 114.3,6.33 IN3-4.15
  Bottom 0.254: v115.57,19.67 132.72,19.67 133.99,18.4 SV2.26
S1
  Top 0.254: IC6.8 114.94,99.05 113.03,97.14 113.03,48.24 110.49,45.7 110.49,33.01 109.22,31.73 SV1.32
  Bottom 0.254: IN1-2.14 85.72,8.24 84.45,6.97 83.19,6.97 82.55,6.33 82.55,4.43 97.16,4.43 97.79,5.07 97.79,6.33 97.16,6.97 95.89,6.97 95.25,7.6 95.25,23.48 103.5,23.48 107.95,27.92 107.95,31.1 108.59,31.1 SV1.32
S2  (via drill 0.61)
  Top 0.254: 135.89,20.3 135.89,45.7 133.99,47.61 133.99,67.3 135.25,68.57 IC8.3 | 135.89,20.3 137.16,19.04 SV2.28 | v134.62,3.8 135.89,5.07 135.89,20.3
  Bottom 0.254: v134.62,3.8 107.95,3.8 107.95,6.33 106.68,7.6 IN3-4.10
T1
  Bottom 0.254: T1GND.2 118.75,31.73 118.11,31.1 112.4,31.1 SV1.34
T2  (via drill 0.61)
  Top 0.254: IC8.6 136.53,60.95 138.43,59.04 138.43,20.3 139.7,19.04 SV2.30 | v109.22,12.05 109.22,8.88 IN3-4.12
  Bottom 0.254: v109.22,12.05 111.76,14.59 132.72,14.59 133.35,15.22 133.35,17.13 137.8,17.13 139.06,18.4 SV2.30
U1  (via drill 0.61)
  Top 0.254: v76.2,21.57 75.56,22.21 75.56,27.29 74.93,27.92 74.93,29.2 73.66,30.46 SV1.4
  Bottom 0.254: IC6.11 114.3,107.3 110.49,103.49 93.98,103.49 91.44,100.95 68.58,100.95 63.5,95.87 63.5,29.83 71.75,29.83 73.03,31.1 SV1.4 | v76.2,21.57 88.9,8.88 IN1-2.16
U2  (via drill 0.61)
  Top 0.254: v144.14,22.21 144.14,58.41 IC8.8 | v114.3,12.05 114.3,11.41 111.76,8.88 IN3-4.14
  Bottom 0.254: v144.14,22.21 144.14,19.04 144.78,19.04 SV2.34 144.14,18.4 143.51,18.4 143.51,15.22 141.61,13.32 115.57,13.32 v114.3,12.05
V1  (via drill 0.61)
  Top 0.254: v111.76,87.62 111.76,106.03 116.84,106.03 120.02,109.21 IC3.3 | v71.12,24.75 69.85,26.02 69.85,29.2 71.12,30.46 SV1.2
  Bottom 0.254: v111.76,87.62 102.87,78.73 102.87,34.91 65.41,34.91 64.14,33.64 64.14,31.1 70.48,31.1 SV1.2 | v71.12,24.75 76.84,24.75 95.89,5.7 IN3-4.1
V2  (via drill 0.61)
  Top 0.254: IC8.11 144.14,66.03 145.42,64.76 145.42,22.21 142.24,19.04 SV2.32 142.24,17.77 140.97,16.49 140.97,15.22 v137.8,12.05
  Bottom 0.254: v137.8,12.05 123.83,12.05 120.02,8.24 114.94,8.24 IN3-4.16
VCC  (via drill 0.61)
  Top 0.508: IC7.14 130.18,74.92 129.54,75.55 129.54,76.19 BYP7.1 | IC8.14 142.88,74.92 142.24,75.55 142.24,76.19 BYP8.1 | v111.76,26.65 104.14,19.04 SV2.2 | BYP6.1 139.7,116.83 139.7,116.19 140.34,115.56 IC4.14 141.61,114.29 142.88,113.02 142.88,93.97 142.24,93.33 JP2.2 | CORE-IO.9 76.84,81.9 78.74,83.81 CORE-IO.12 78.74,85.08 78.74,98.41 79.38,99.05 79.38,113.02 78.11,114.29 IC1.14 76.84,115.56 76.2,116.19 76.2,116.83 BYP1.1 | IC3.14 127.64,115.56 127,116.19 127,116.83 BYP5.1 | IC6.14 114.94,115.56 114.3,116.19 114.3,116.83 BYP4.1 | IC5.14 102.23,115.56 101.6,116.19 101.6,116.83 BYP3.1 | IC2.14 89.53,115.56 88.9,116.19 88.9,116.83 BYP2.1
  Bottom 0.508: v111.76,26.65 113.03,27.92 132.08,27.92 140.97,36.81 140.97,73.01 | 140.97,73.01 140.97,74.28 142.24,74.28 IC8.14 | 140.97,73.01 133.35,73.01 132.08,74.28 IC7.14 | 138.43,94.6 140.97,94.6 142.24,93.33 JP2.2 | 138.43,94.6 122.56,94.6 120.02,92.06 BYP10.1 | 87,116.19 80.01,116.19 78.74,114.92 IC1.14 | 87,116.19 88.27,117.46 BYP2.1 | 99.69,116.19 100.97,117.46 BYP3.1 | 99.69,116.19 87,116.19 | 112.4,116.19 113.66,117.46 BYP4.1 | 112.4,116.19 99.69,116.19 | 125.09,116.19 126.36,117.46 BYP5.1 | 125.09,116.19 112.4,116.19 | 125.09,116.19 137.8,116.19 139.06,117.46 BYP6.1 | 138.43,94.6 138.43,81.27 142.24,77.46 BYP8.1

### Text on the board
Top: Component Side | PA8PDP/VRS
Bottom: Solder Side
tValues: - | + | + | - | FlipChip Tester - Rev.1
